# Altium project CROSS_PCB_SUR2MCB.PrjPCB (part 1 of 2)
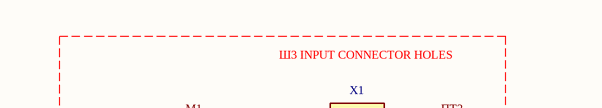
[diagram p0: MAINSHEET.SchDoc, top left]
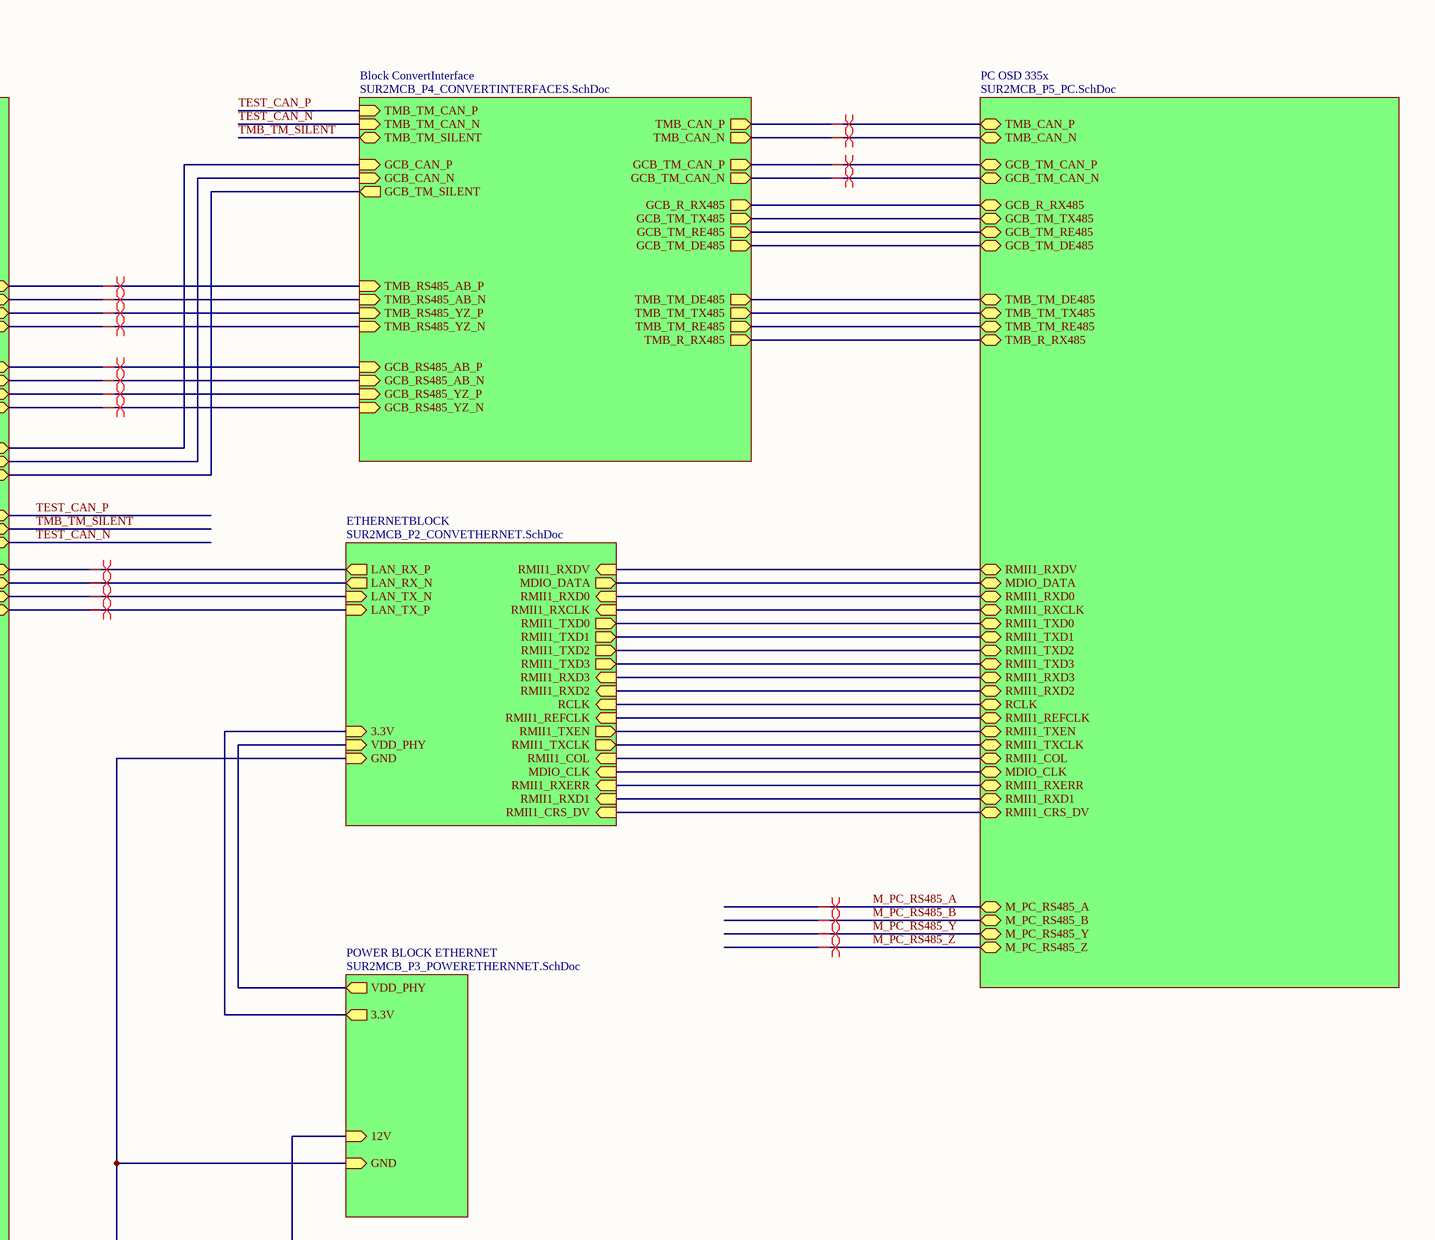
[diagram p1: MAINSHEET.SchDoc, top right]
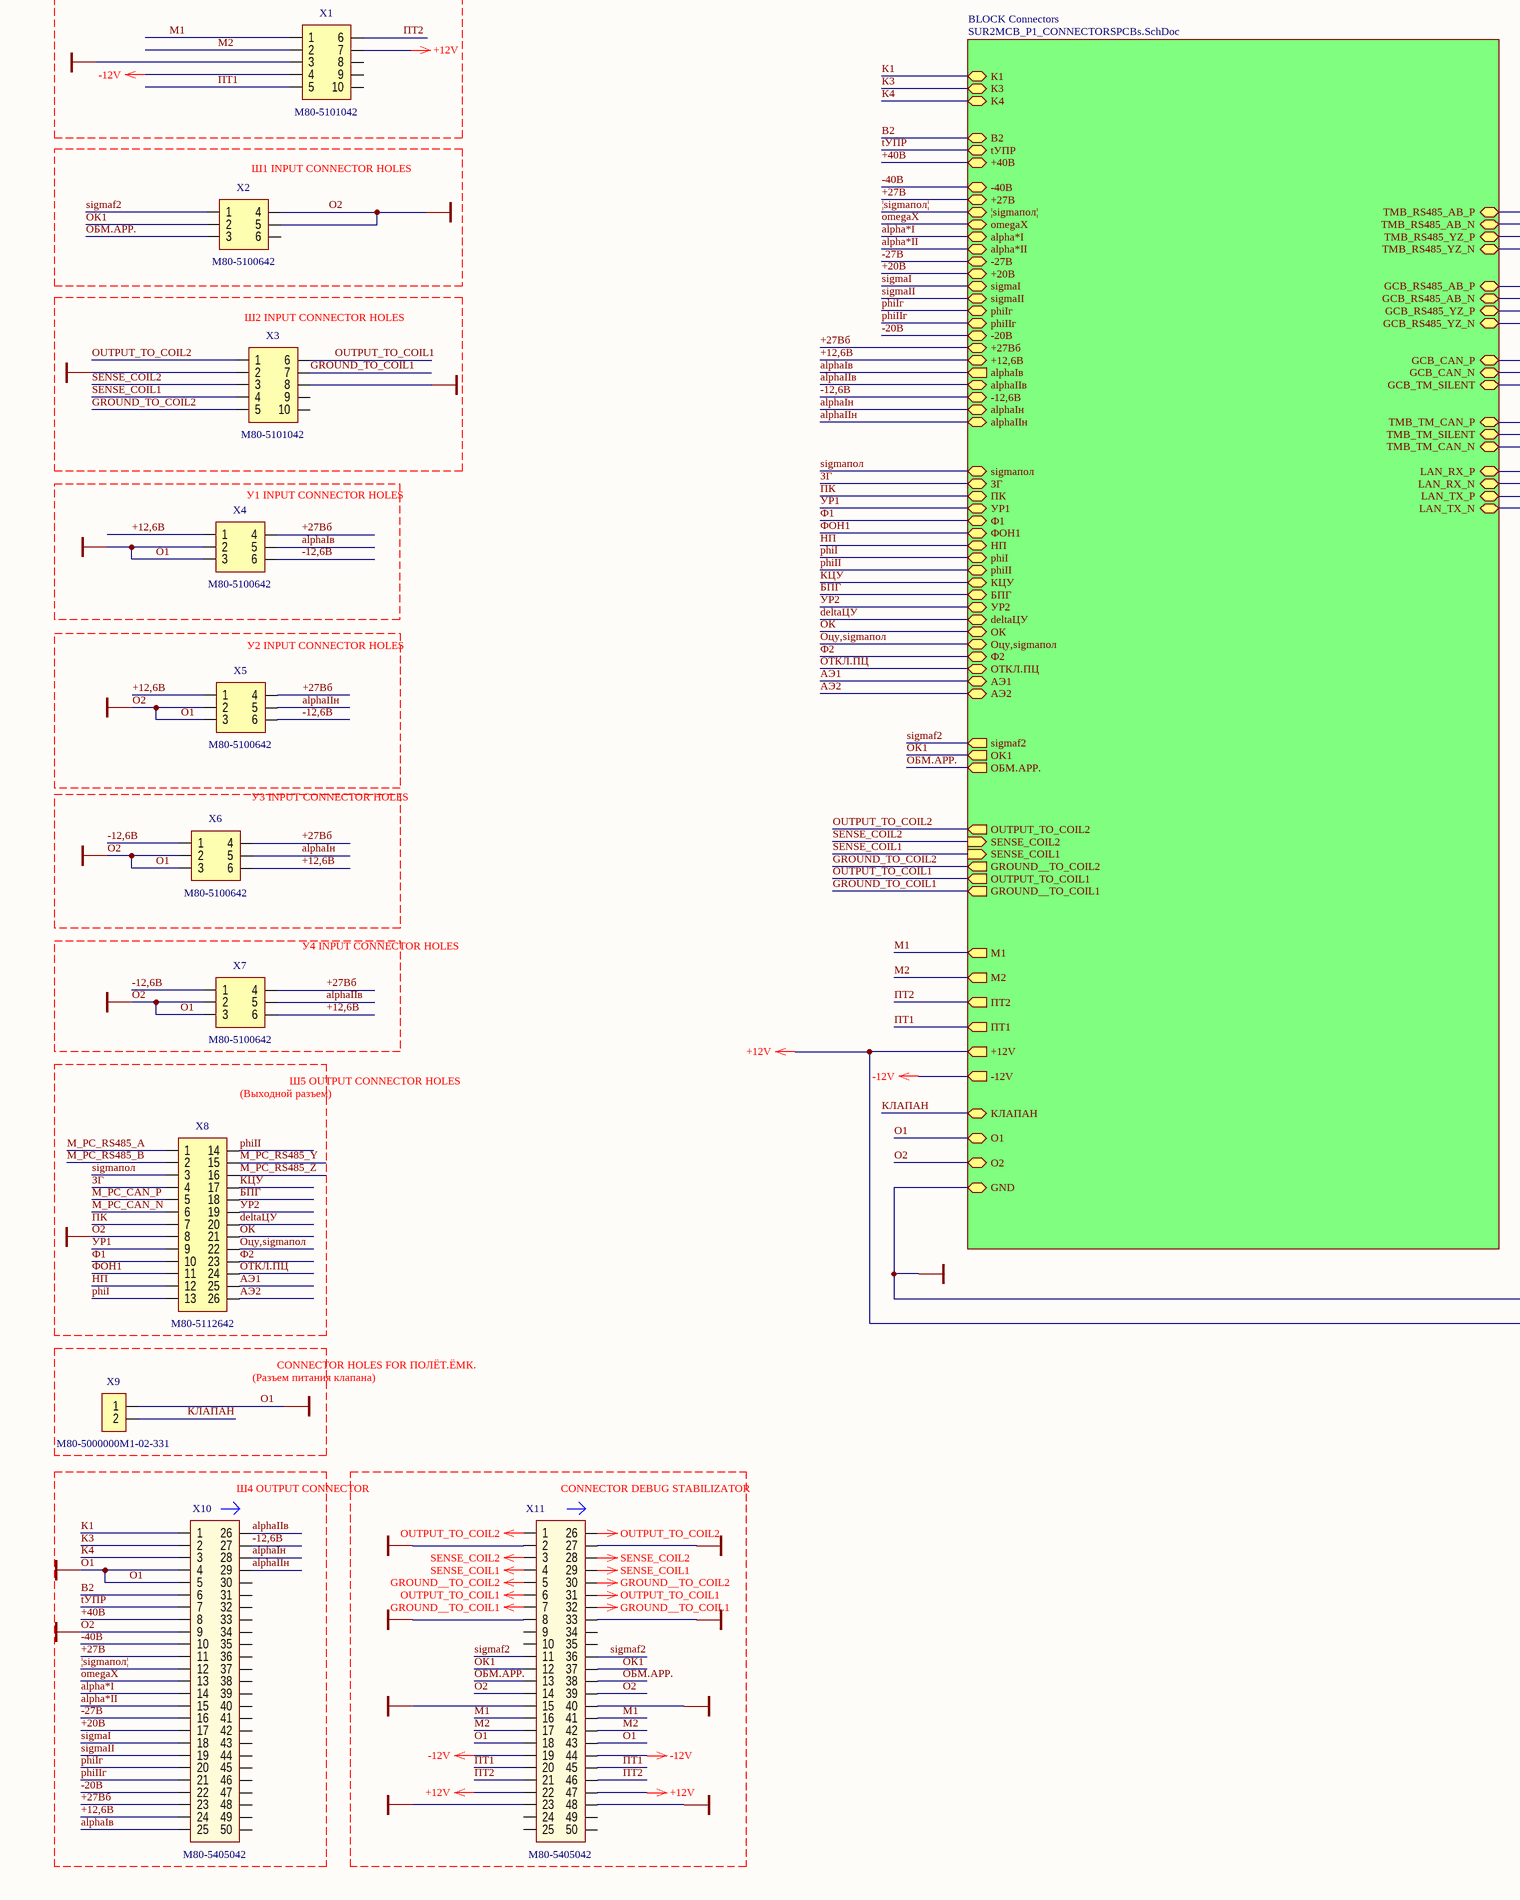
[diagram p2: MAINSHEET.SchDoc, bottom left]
7 sheets, 142 parts. Net scope: hierarchical (ports join the sheet entries above them; power ports are global).
Board file: SUR2MCB.PcbDoc
Sheets:
  MAINSHEET.SchDoc
    BLOCK Connectors = SUR2MCB_P1_CONNECTORSPCBs.SchDoc
    ETHERNETBLOCK = SUR2MCB_P2_CONVETHERNET.SchDoc
    PC OSD 335x = SUR2MCB_P5_PC.SchDoc
    POWER BLOCK ETHERNET = SUR2MCB_P3_POWERETHERNNET.SchDoc
    Block ConvertInterface = SUR2MCB_P4_CONVERTINTERFACES.SchDoc
  Struct_E1.SchDoc

## Sheet MAINSHEET.SchDoc
size 594 x 420 mm; Scale: 1:1; Разраб.: Иванов; Обозначение документа: АБВГ.123456.001 Э3; Пров.: Петров; Утв.: Сидоров; Наименование организации: ОАО "Концерн "МПО-Гидроприбор"; Перв. применение: АБВГ.123456.000; Наименование изделия 1: Плата; Наименование изделия 2: Схема электрическая; Наименование изделия 3: принципиальная; Нач. отд.: Нач. отд.; Фамилия нач. отд.: Сидоров

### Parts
X1  value M80-5101042  [M80-5101042]
X2  value M80-5100642  [M80-5100642]
X3  value M80-5101042  [M80-5101042]
X4  value M80-5100642  [M80-5100642]
X5  value M80-5100642  [M80-5100642]
X6  value M80-5100642  [M80-5100642]
X7  value M80-5100642  [M80-5100642]
X8  value M80-5112642  [M80-5112642_HOR]
X9  value M80-5000000M1-02-331  [M80-5000000M1-02-331]
X10  value M80-5405042  [M80-5405042]
X11  value M80-5405042  [M80-5405042]

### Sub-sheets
BLOCK Connectors = SUR2MCB_P1_CONNECTORSPCBs.SchDoc: tУПР (bidir), B2 (bidir), K4 (bidir), +40В (bidir), К1 (bidir), К3 (bidir), OUTPUT_TO_COIL2 (out), OUTPUT_TO_COIL1 (out), GROUND__TO_COIL1 (out), SENSE_COIL2 (in), GROUND__TO_COIL2 (out), SENSE_COIL1 (in), M1 (out), КЛАПАН (bidir), О1 (bidir), O2 (bidir), TMB_RS485_AB_N (bidir), TMB_RS485_AB_P (bidir), TMB_RS485_YZ_N (bidir), TMB_RS485_YZ_P (bidir), LAN_RX_P (bidir), LAN_RX_N (bidir), LAN_TX_P (bidir), LAN_TX_N (bidir), GCB_RS485_AB_N (bidir), GCB_RS485_YZ_N (bidir), GCB_RS485_YZ_P (bidir), GCB_RS485_AB_P (bidir), GCB_CAN_P (bidir), GCB_CAN_N (bidir), GCB_TM_SILENT (bidir), TMB_TM_CAN_P (bidir), TMB_TM_SILENT (bidir), TMB_TM_CAN_N (bidir), -40В (bidir), +27В (bidir), ¦sigmaпол¦ (bidir), omegaX (bidir), alpha*II (bidir), alpha*I (bidir), -27В (bidir), +20В (bidir), -20В (bidir), sigmaII (bidir), sigmaI (bidir), phiIIг (bidir), phiIг (bidir), +27Вб (bidir), +12,6В (bidir), -12,6В (bidir), alphaIв (out), alphaIIв (bidir), alphaIIн (bidir), alphaIн (bidir), sigmaпол (bidir), ЗГ (bidir), ПК (bidir), УР1 (bidir), Ф1 (bidir), ФОН1 (bidir), НП (bidir), phiI (bidir), phiII (bidir), ПТ2 (out), +12V (out), КЦУ (bidir), БПГ (bidir), УР2 (bidir), deltaЦУ (bidir), ОК (bidir), Оцу,sigmaпол (bidir), Ф2 (bidir), ОТКЛ.ПЦ (bidir), АЭ1 (bidir), АЭ2 (bidir), ПТ1 (out), M2 (out), -12V (out), sigmaf2 (out), OK1 (out), ОБМ.АРР. (out), GND (bidir)
Block ConvertInterface = SUR2MCB_P4_CONVERTINTERFACES.SchDoc: TMB_TM_TX485 (out), GCB_RS485_YZ_P (in), TMB_R_RX485 (out), GCB_RS485_YZ_N (in), GCB_RS485_AB_P (in), TMB_TM_RE485 (out), GCB_TM_CAN_P (out), TMB_TM_DE485 (out), GCB_TM_CAN_N (out), GCB_RS485_AB_N (in), TMB_RS485_YZ_N (in), GCB_TM_RE485 (out), GCB_CAN_P (in), GCB_R_RX485 (out), GCB_TM_TX485 (out), TMB_RS485_AB_P (in), GCB_TM_SILENT (out), GCB_CAN_N (in), TMB_RS485_YZ_P (in), TMB_RS485_AB_N (in), GCB_TM_DE485 (out), TMB_TM_SILENT (bidir), TMB_TM_CAN_P (in), TMB_TM_CAN_N (in), TMB_CAN_P (out), TMB_CAN_N (out)
ETHERNETBLOCK = SUR2MCB_P2_CONVETHERNET.SchDoc: RMII1_RXDV (in), MDIO_DATA (out), RMII1_RXD0 (in), RMII1_RXCLK (in), RMII1_TXD0 (out), RMII1_TXD2 (out), RMII1_TXD3 (out), RMII1_RXD3 (in), RMII1_RXD2 (in), LAN_RX_P (out), RCLK (in), LAN_RX_N (out), LAN_TX_N (in), RMII1_REFCLK (in), RMII1_TXEN (out), LAN_TX_P (in), RMII1_TXCLK (out), RMII1_COL (in), MDIO_CLK (in), RMII1_TXD1 (out), GND (in), VDD_PHY (in), 3.3V (in), RMII1_RXERR (in), RMII1_RXD1 (in), RMII1_CRS_DV (in)
PC OSD 335x = SUR2MCB_P5_PC.SchDoc: GCB_R_RX485 (bidir), GCB_TM_CAN_N (bidir), GCB_TM_RE485 (bidir), GCB_TM_TX485 (bidir), TMB_TM_DE485 (bidir), GCB_TM_DE485 (bidir), TMB_TM_RE485 (bidir), TMB_TM_TX485 (bidir), TMB_R_RX485 (bidir), RMII1_TXCLK (bidir), GCB_TM_CAN_P (bidir), TMB_CAN_N (bidir), TMB_CAN_P (bidir), RMII1_TXD0 (bidir), RMII1_CRS_DV (bidir), RMII1_TXD2 (bidir), MDIO_CLK (bidir), RMII1_RXDV (bidir), RMII1_TXD1 (bidir), RMII1_TXEN (bidir), RMII1_RXD3 (bidir), RMII1_RXERR (bidir), RMII1_TXD3 (bidir), RMII1_RXD0 (bidir), MDIO_DATA (bidir), RMII1_RXD2 (bidir), RMII1_RXD1 (bidir), RMII1_COL (bidir), RMII1_RXCLK (bidir), RMII1_REFCLK (bidir), RCLK (bidir), M_PC_RS485_Z (bidir), M_PC_RS485_Y (bidir), M_PC_RS485_B (bidir), M_PC_RS485_A (bidir)
POWER BLOCK ETHERNET = SUR2MCB_P3_POWERETHERNNET.SchDoc: 12V (in), VDD_PHY (out), 3.3V (out), GND (in)

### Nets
+12V: X1.7 X11.22 X11.47 ; sheet BLOCK Connectors/+12V, sheet POWER BLOCK ETHERNET/12V
-12V: X1.4 X11.19 X11.44 ; sheet BLOCK Connectors/-12V
GROUND_TO_COIL1: X3.7 X11.7 X11.32 ; sheet BLOCK Connectors/GROUND__TO_COIL1  [also labelled GROUND__TO_COIL1]
GROUND_TO_COIL2: X3.5 X11.5 X11.30 ; sheet BLOCK Connectors/GROUND__TO_COIL2  [also labelled GROUND__TO_COIL2]
OUTPUT_TO_COIL1: X3.6 X11.6 X11.31 ; sheet BLOCK Connectors/OUTPUT_TO_COIL1
OUTPUT_TO_COIL2: X3.1 X11.1 X11.26 ; sheet BLOCK Connectors/OUTPUT_TO_COIL2
RMII1_REFCLK: sheet ETHERNETBLOCK/RMII1_REFCLK, sheet PC OSD 335x/RMII1_REFCLK
SENSE_COIL1: X3.4 X11.4 X11.29 ; sheet BLOCK Connectors/SENSE_COIL1
SENSE_COIL2: X3.3 X11.3 X11.28 ; sheet BLOCK Connectors/SENSE_COIL2
VDD_3.3V: sheet ETHERNETBLOCK/3.3V, sheet POWER BLOCK ETHERNET/3.3V
VDD_PHY: sheet ETHERNETBLOCK/VDD_PHY, sheet POWER BLOCK ETHERNET/VDD_PHY
О1: X1.3 X2.4 X2.5 X3.2 X3.8 X4.2 X4.3 X5.2 X5.3 X6.2 X6.3 X7.2 X7.3 X8.8 X9.1 X10.4 X10.5 X10.9 X11.2 X11.8 X11.14 X11.15 X11.18 X11.23 X11.27 X11.33 X11.39 X11.40 X11.43 X11.48 ; sheet BLOCK Connectors/О1, sheet BLOCK Connectors/O2, sheet BLOCK Connectors/GND, sheet ETHERNETBLOCK/GND, sheet POWER BLOCK ETHERNET/GND  [also labelled GND, О2]
+12,6В: X4.1 X5.1 X6.6 X7.6 X10.24 ; sheet BLOCK Connectors/+12,6В
+20В: X10.17 ; sheet BLOCK Connectors/+20В
+27В: X10.11 ; sheet BLOCK Connectors/+27В
+27Вб: X4.4 X5.4 X6.4 X7.4 X10.23 ; sheet BLOCK Connectors/+27Вб
+40В: X10.8 ; sheet BLOCK Connectors/+40В
-12,6В: X4.6 X5.6 X6.1 X7.1 X10.27 ; sheet BLOCK Connectors/-12,6В
-20В: X10.22 ; sheet BLOCK Connectors/-20В
-27В: X10.16 ; sheet BLOCK Connectors/-27В
-40В: X10.10 ; sheet BLOCK Connectors/-40В
alpha*I: X10.14 ; sheet BLOCK Connectors/alpha*I
alpha*II: X10.15 ; sheet BLOCK Connectors/alpha*II
alphaIIв: X4.5 X5.5 X6.5 X7.5 X10.25 X10.26 X10.28 X10.29 ; sheet BLOCK Connectors/alphaIв, sheet BLOCK Connectors/alphaIIв, sheet BLOCK Connectors/alphaIIн, sheet BLOCK Connectors/alphaIн  [also labelled alphaIIн, alphaIв, alphaIн]
deltaЦУ: X8.20 ; sheet BLOCK Connectors/deltaЦУ
GCB_CAN_N: sheet BLOCK Connectors/GCB_CAN_N, sheet Block ConvertInterface/GCB_CAN_N
GCB_CAN_P: sheet BLOCK Connectors/GCB_CAN_P, sheet Block ConvertInterface/GCB_CAN_P
GCB_R_RX485: sheet PC OSD 335x/GCB_R_RX485, sheet Block ConvertInterface/GCB_R_RX485
GCB_RS485_AB_N: sheet BLOCK Connectors/GCB_RS485_AB_N, sheet Block ConvertInterface/GCB_RS485_AB_N
GCB_RS485_AB_P: sheet BLOCK Connectors/GCB_RS485_AB_P, sheet Block ConvertInterface/GCB_RS485_AB_P
GCB_RS485_YZ_N: sheet BLOCK Connectors/GCB_RS485_YZ_N, sheet Block ConvertInterface/GCB_RS485_YZ_N
GCB_RS485_YZ_P: sheet BLOCK Connectors/GCB_RS485_YZ_P, sheet Block ConvertInterface/GCB_RS485_YZ_P
GCB_TM_CAN_N: sheet PC OSD 335x/GCB_TM_CAN_N, sheet Block ConvertInterface/GCB_TM_CAN_N
GCB_TM_CAN_P: sheet PC OSD 335x/GCB_TM_CAN_P, sheet Block ConvertInterface/GCB_TM_CAN_P
GCB_TM_DE485: sheet PC OSD 335x/GCB_TM_DE485, sheet Block ConvertInterface/GCB_TM_DE485
GCB_TM_RE485: sheet PC OSD 335x/GCB_TM_RE485, sheet Block ConvertInterface/GCB_TM_RE485
GCB_TM_SILENT: sheet BLOCK Connectors/GCB_TM_SILENT, sheet Block ConvertInterface/GCB_TM_SILENT
GCB_TM_TX485: sheet PC OSD 335x/GCB_TM_TX485, sheet Block ConvertInterface/GCB_TM_TX485
LAN_RX_N: sheet BLOCK Connectors/LAN_RX_N, sheet ETHERNETBLOCK/LAN_RX_N
LAN_RX_P: sheet BLOCK Connectors/LAN_RX_P, sheet ETHERNETBLOCK/LAN_RX_P
LAN_TX_N: sheet BLOCK Connectors/LAN_TX_N, sheet ETHERNETBLOCK/LAN_TX_P
LAN_TX_N: sheet BLOCK Connectors/LAN_TX_P, sheet ETHERNETBLOCK/LAN_TX_N  [a separate net that carries the same name]
M_PC_CAN_N: X8.6
M_PC_CAN_P: X8.5
M_PC_RS485_A: X8.1 ; sheet PC OSD 335x/M_PC_RS485_A
M_PC_RS485_B: X8.2 ; sheet PC OSD 335x/M_PC_RS485_B
M_PC_RS485_Y: X8.15 ; sheet PC OSD 335x/M_PC_RS485_Y
M_PC_RS485_Z: X8.16 ; sheet PC OSD 335x/M_PC_RS485_Z
MDIO_CLK: sheet ETHERNETBLOCK/MDIO_CLK, sheet PC OSD 335x/MDIO_CLK
MDIO_DATA: sheet ETHERNETBLOCK/MDIO_DATA, sheet PC OSD 335x/MDIO_DATA
omegaX: X10.13 ; sheet BLOCK Connectors/omegaX
phiI: X8.13 ; sheet BLOCK Connectors/phiI
phiII: X8.14 ; sheet BLOCK Connectors/phiII
phiIIг: X10.21 ; sheet BLOCK Connectors/phiIIг
phiIг: X10.20 ; sheet BLOCK Connectors/phiIг
RCLK: sheet ETHERNETBLOCK/RCLK, sheet PC OSD 335x/RCLK
RMII1_COL: sheet ETHERNETBLOCK/RMII1_COL, sheet PC OSD 335x/RMII1_COL
RMII1_CRS_DV: sheet ETHERNETBLOCK/RMII1_CRS_DV, sheet PC OSD 335x/RMII1_CRS_DV
RMII1_RXCLK: sheet ETHERNETBLOCK/RMII1_RXCLK, sheet PC OSD 335x/RMII1_RXCLK
RMII1_RXD0: sheet ETHERNETBLOCK/RMII1_RXD0, sheet PC OSD 335x/RMII1_RXD0
RMII1_RXD1: sheet ETHERNETBLOCK/RMII1_RXD1, sheet PC OSD 335x/RMII1_RXD1
RMII1_RXD2: sheet ETHERNETBLOCK/RMII1_RXD2, sheet PC OSD 335x/RMII1_RXD2
RMII1_RXD3: sheet ETHERNETBLOCK/RMII1_RXD3, sheet PC OSD 335x/RMII1_RXD3
RMII1_RXDV: sheet ETHERNETBLOCK/RMII1_RXDV, sheet PC OSD 335x/RMII1_RXDV
RMII1_RXERR: sheet ETHERNETBLOCK/RMII1_RXERR, sheet PC OSD 335x/RMII1_RXERR
RMII1_TXCLK: sheet ETHERNETBLOCK/RMII1_TXCLK, sheet PC OSD 335x/RMII1_TXCLK
RMII1_TXD0: sheet ETHERNETBLOCK/RMII1_TXD0, sheet PC OSD 335x/RMII1_TXD0
RMII1_TXD1: sheet ETHERNETBLOCK/RMII1_TXD1, sheet PC OSD 335x/RMII1_TXD1
RMII1_TXD2: sheet ETHERNETBLOCK/RMII1_TXD2, sheet PC OSD 335x/RMII1_TXD2
RMII1_TXD3: sheet ETHERNETBLOCK/RMII1_TXD3, sheet PC OSD 335x/RMII1_TXD3
RMII1_TXEN: sheet ETHERNETBLOCK/RMII1_TXEN, sheet PC OSD 335x/RMII1_TXEN
sigmaf2: X2.1 X11.11 X11.36 ; sheet BLOCK Connectors/sigmaf2
sigmaI: X10.18 ; sheet BLOCK Connectors/sigmaI
sigmaII: X10.19 ; sheet BLOCK Connectors/sigmaII
sigmaпол: X8.3 ; sheet BLOCK Connectors/sigmaпол
TEST_CAN_N: sheet BLOCK Connectors/TMB_TM_CAN_N, sheet Block ConvertInterface/TMB_TM_CAN_N
TEST_CAN_P: sheet BLOCK Connectors/TMB_TM_CAN_P, sheet Block ConvertInterface/TMB_TM_CAN_P
TMB_CAN_N: sheet PC OSD 335x/TMB_CAN_N, sheet Block ConvertInterface/TMB_CAN_N
TMB_CAN_P: sheet PC OSD 335x/TMB_CAN_P, sheet Block ConvertInterface/TMB_CAN_P
TMB_R_RX485: sheet PC OSD 335x/TMB_R_RX485, sheet Block ConvertInterface/TMB_R_RX485
TMB_RS485_AB_N: sheet BLOCK Connectors/TMB_RS485_AB_N, sheet Block ConvertInterface/TMB_RS485_AB_N
TMB_RS485_AB_P: sheet BLOCK Connectors/TMB_RS485_AB_P, sheet Block ConvertInterface/TMB_RS485_AB_P
TMB_RS485_YZ_N: sheet BLOCK Connectors/TMB_RS485_YZ_N, sheet Block ConvertInterface/TMB_RS485_YZ_N
TMB_RS485_YZ_P: sheet BLOCK Connectors/TMB_RS485_YZ_P, sheet Block ConvertInterface/TMB_RS485_YZ_P
TMB_TM_DE485: sheet PC OSD 335x/TMB_TM_DE485, sheet Block ConvertInterface/TMB_TM_DE485
TMB_TM_RE485: sheet PC OSD 335x/TMB_TM_RE485, sheet Block ConvertInterface/TMB_TM_RE485
TMB_TM_SILENT: sheet BLOCK Connectors/TMB_TM_SILENT, sheet Block ConvertInterface/TMB_TM_SILENT
TMB_TM_TX485: sheet PC OSD 335x/TMB_TM_TX485, sheet Block ConvertInterface/TMB_TM_TX485
tУПР: X10.7 ; sheet BLOCK Connectors/tУПР
¦sigmaпол¦: X10.12 ; sheet BLOCK Connectors/¦sigmaпол¦
АЭ1: X8.25 ; sheet BLOCK Connectors/АЭ1
АЭ2: X8.26 ; sheet BLOCK Connectors/АЭ2
БПГ: X8.18 ; sheet BLOCK Connectors/БПГ
В2: X10.6 ; sheet BLOCK Connectors/B2
ЗГ: X8.4 ; sheet BLOCK Connectors/ЗГ
К1: X10.1 ; sheet BLOCK Connectors/К1
К3: X10.2 ; sheet BLOCK Connectors/К3
К4: X10.3 ; sheet BLOCK Connectors/K4
КЛАПАН: X9.2 ; sheet BLOCK Connectors/КЛАПАН
КЦУ: X8.17 ; sheet BLOCK Connectors/КЦУ
М1: X1.1 X11.16 X11.41 ; sheet BLOCK Connectors/M1
М2: X1.2 X11.17 X11.42 ; sheet BLOCK Connectors/M2
НП: X8.12 ; sheet BLOCK Connectors/НП
ОБМ.АРР.: X2.3 X11.13 X11.38 ; sheet BLOCK Connectors/ОБМ.АРР.
ОК: X8.21 ; sheet BLOCK Connectors/ОК
ОК1: X2.2 X11.12 X11.37 ; sheet BLOCK Connectors/OK1
ОТКЛ.ПЦ: X8.24 ; sheet BLOCK Connectors/ОТКЛ.ПЦ
Оцу,sigmaпол: X8.22 ; sheet BLOCK Connectors/Оцу,sigmaпол
ПК: X8.7 ; sheet BLOCK Connectors/ПК
ПТ1: X1.5 X11.20 X11.45 ; sheet BLOCK Connectors/ПТ1
ПТ2: X1.6 X11.21 X11.46 ; sheet BLOCK Connectors/ПТ2
УР1: X8.9 ; sheet BLOCK Connectors/УР1
УР2: X8.19 ; sheet BLOCK Connectors/УР2
Ф1: X8.10 ; sheet BLOCK Connectors/Ф1
Ф2: X8.23 ; sheet BLOCK Connectors/Ф2
ФОН1: X8.11 ; sheet BLOCK Connectors/ФОН1

Not connected (* = marked no-connect by the designer): X1 8 9 10; X2 6; X3 9 10; X10 30 31 32 33 34 35 36 37 38 39 40 41 42 43 44 45 46 47 48 49 50; X11 9 10 24 25 34 35 49 50

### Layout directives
differential pair: GCB_RS485_AB_N, GCB_RS485_AB_P, GCB_RS485_YZ_N, GCB_RS485_YZ_P, GCB_TM_CAN_N, GCB_TM_CAN_P, LAN_RX_N, LAN_RX_P, LAN_TX_N, M_PC_RS485_A, M_PC_RS485_B, M_PC_RS485_Y, M_PC_RS485_Z, TMB_CAN_N, TMB_CAN_P, TMB_RS485_AB_N, TMB_RS485_AB_P, TMB_RS485_YZ_N, TMB_RS485_YZ_P

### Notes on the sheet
- Ш3 INPUT CONNECTOR HOLES
- (near X2) Ш1 INPUT CONNECTOR HOLES
- (near X3) Ш2 INPUT CONNECTOR HOLES
- (near X4) У1 INPUT CONNECTOR HOLES
- (near X5) У2 INPUT CONNECTOR HOLES
- (near X6) У3 INPUT CONNECTOR HOLES
- (near X7) У4 INPUT CONNECTOR HOLES
- (Выходной разъем)
- Ш5 OUTPUT CONNECTOR HOLES
- (near X9) CONNECTOR HOLES FOR ПОЛЁТ.ЁМК.
- (near X9) (Разъем питания клапана)
- (near X10) Ш4 OUTPUT CONNECTOR
- (near X11) CONNECTOR DEBUG STABILIZATOR

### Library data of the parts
X1 X3 = M80-5101042: J-TEK 10 POS DIL MALE 2.0MM 2.2A 800V; ValueManufacturer: Harvin Inc.; PowerVoltage: 2.2A, 800V; ValueDescription: M80-5101042 Вилка Harvin Inc.  6.05x20.4mm  2.2A, 800V; ValueType: Connector
X2 X4-X7 = M80-5100642: J-TEK 6 POS DIL MALE 2.0MM 2.2A 800V; ValueManufacturer: Harvin Inc.; PowerVoltage: 2.2A, 800V; ValueDescription: M80-5100642 Вилка Harvin Inc.  6.05x16.4mm  2.2A, 800V; ValueType: Connector
X8 = M80-5112642_HOR: J-TEK 26 POS DIL MALE 2.0MM 2.2A 800V; ValueManufacturer: Harvin Inc.; PowerVoltage: 2.2A, 800V; ValueDescription: M80-5112642 Вилка Harvin Inc.  6.05x36mm  2.2A, 800V; ValueType: Connector
X9 = M80-5000000M1-02-331: MIX-TEK 2 POS DIL MALE 4.0MM 20A 600V; ValueManufacturer: Harvin Inc.; PowerVoltage: 20A, 600V; ValueDescription: M80-5000000M1-02-331 Вилка Harvin Inc.  6.05x18.4mm  20A, 600V; ValueType: Connector
X10 X11 = M80-5405042: CONN HDR 2MM R/A W/SCREW 50POS; ValueManufacturer: Harwin Inc.; PowerVoltage: 2.2A, 800V; TechSpec: 3A; ValueDescription: M80-5405042 Вилка Harwin Inc.  10x60mm  3A; ValueType: Male Socket

## Sheet SUR2MCB_P1_CONNECTORSPCBs.SchDoc
size 420 x 297 mm; Scale: 1:1; Разраб.: Иванов; Обозначение документа: АБВГ.123456.001 Э3; Пров.: Петров; Утв.: Сидоров; Наименование организации: ОАО "Концерн "МПО-Гидроприбор"; Перв. применение: АБВГ.123456.000; Наименование изделия 1: Плата; Наименование изделия 2: Схема электрическая; Наименование изделия 3: принципиальная; Нач. отд.: Нач. отд.; Фамилия нач. отд.: Сидоров
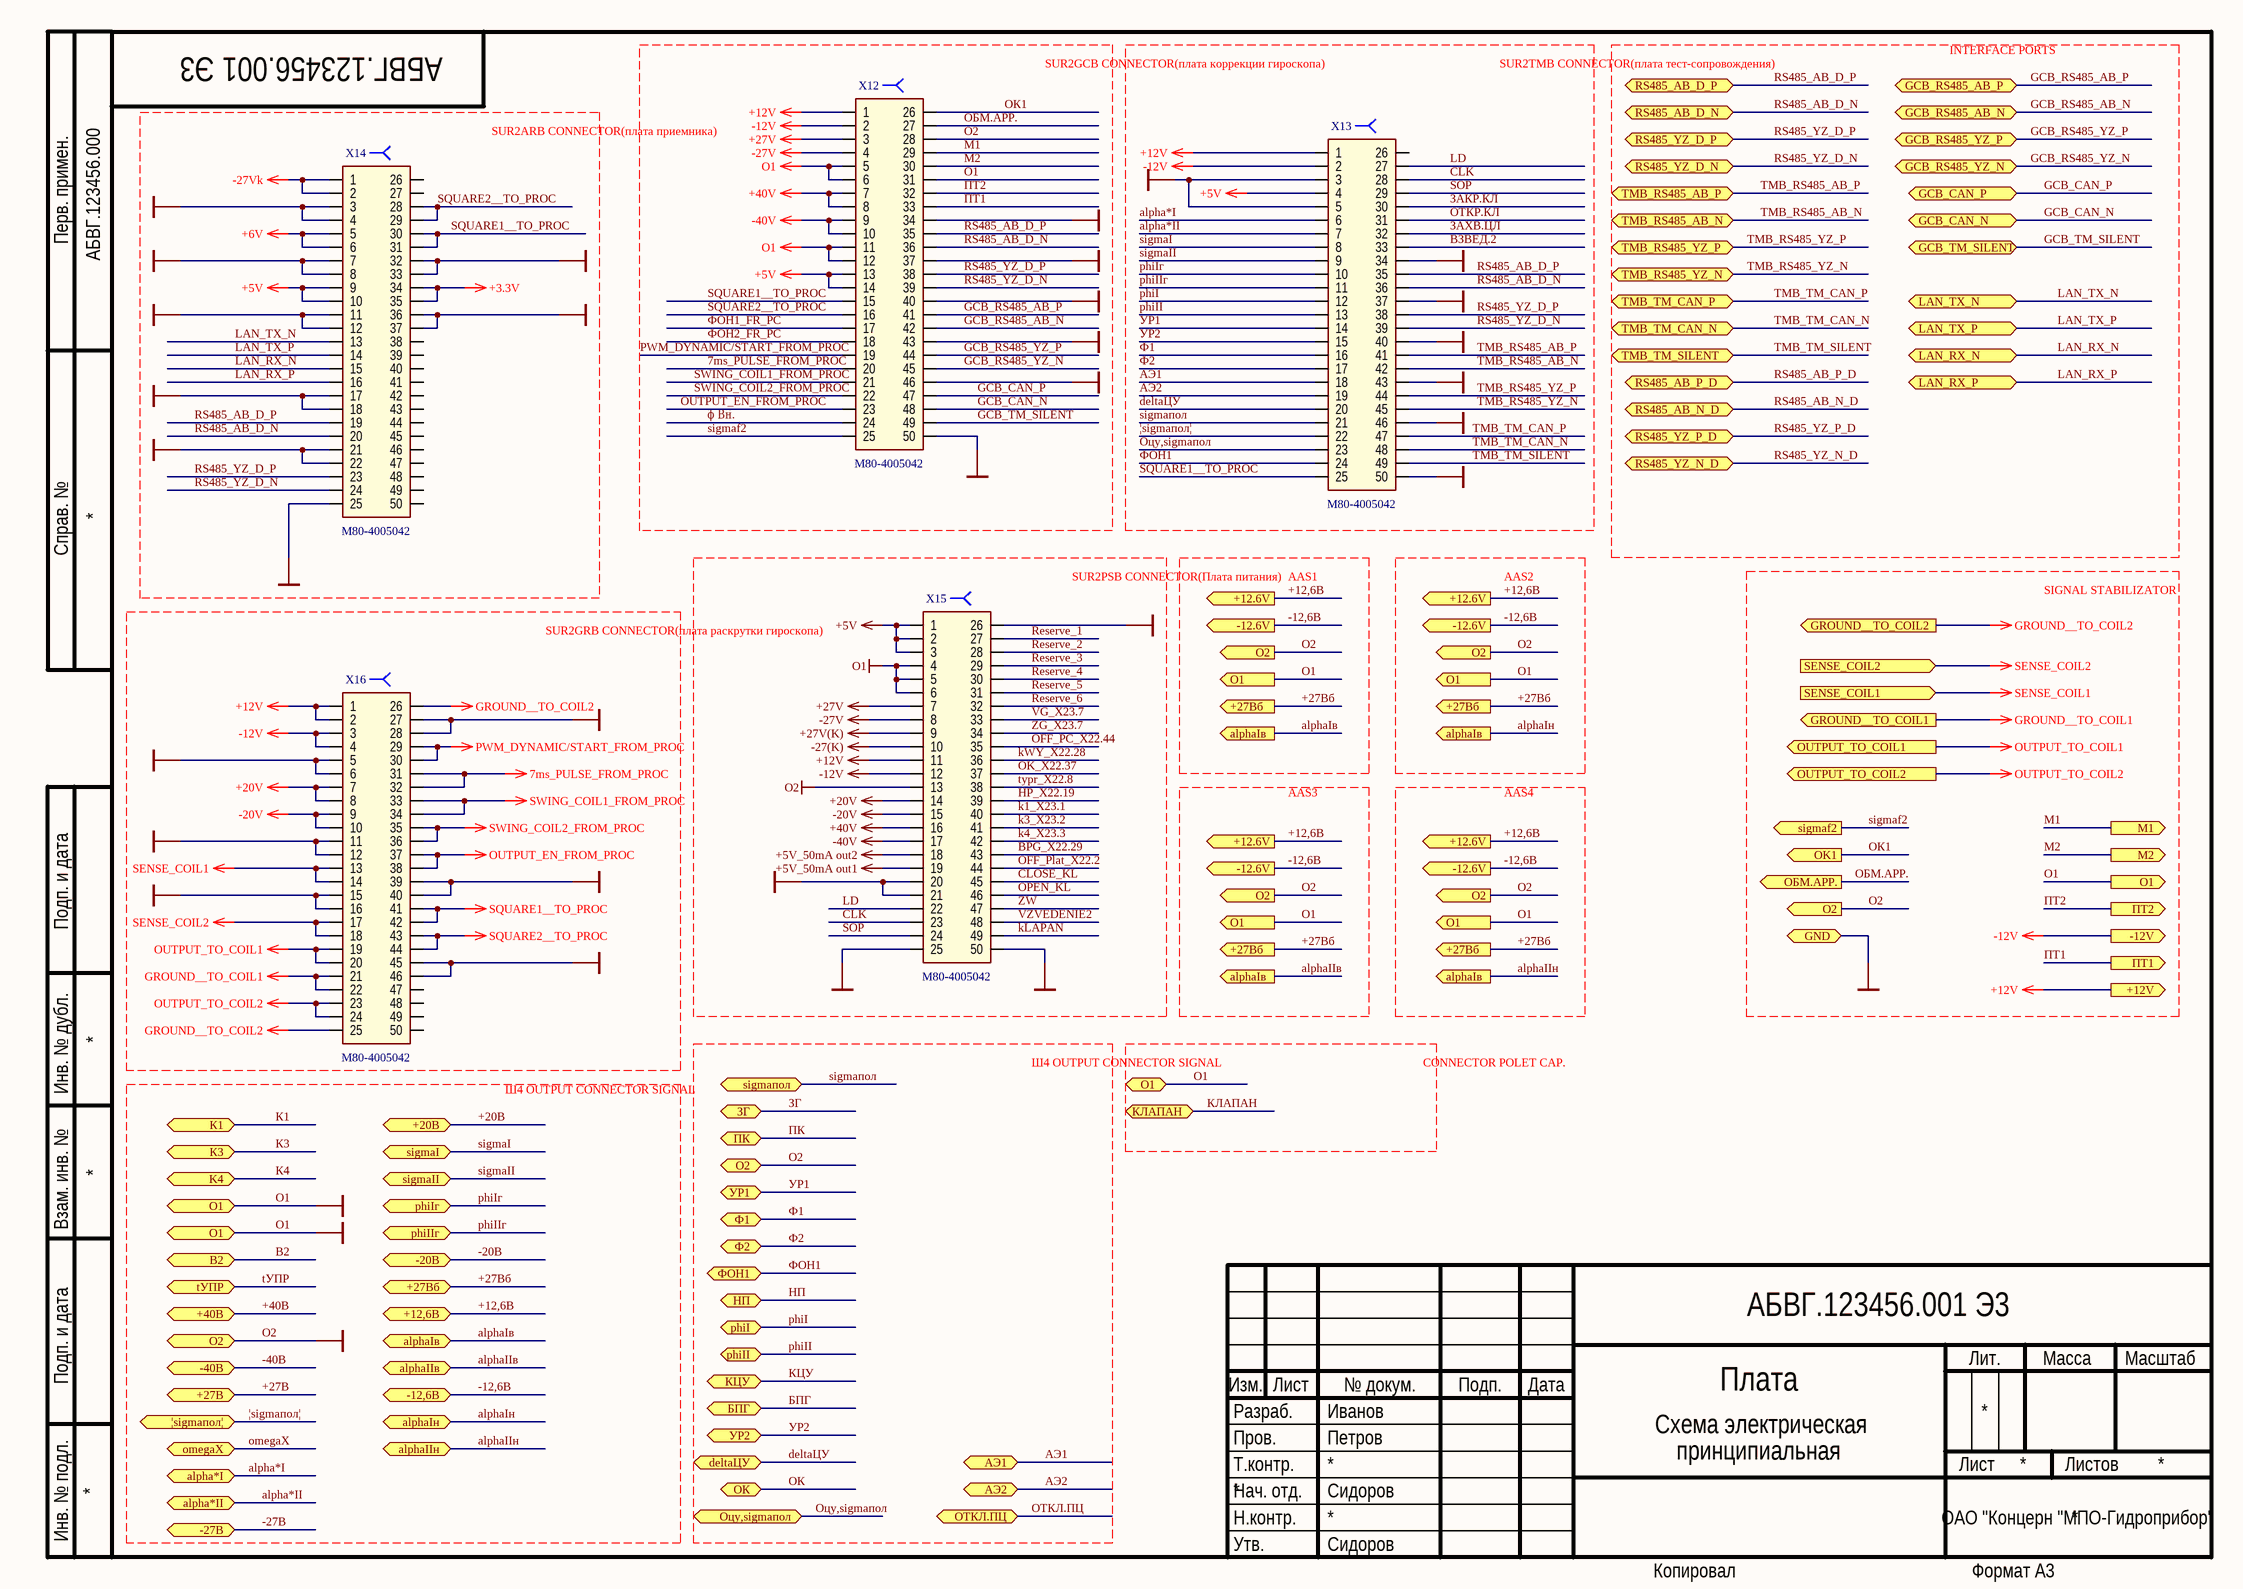
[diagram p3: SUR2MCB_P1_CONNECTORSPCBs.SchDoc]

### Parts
X12  value M80-4005042  [M80-4005042]
X13  value M80-4005042  [M80-4005042]
X14  value M80-4005042  [M80-4005042]
X15  value M80-4005042  [M80-4005042]
X16  value M80-4005042  [M80-4005042]

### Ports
+12,6В (bidir), +12.6V (out), +12V (out), +20В (bidir), +27В (bidir), +27Вб (bidir), +27Вб (out), +40В (bidir), -12,6В (bidir), -12.6V (out), -12V (out), -20В (bidir), -27В (bidir), -40В (bidir), alpha*I (bidir), alpha*II (bidir), alphaIIв (bidir), alphaIIн (bidir), alphaIв (bidir), alphaIв (out), alphaIн (bidir), B2 (bidir), deltaЦУ (bidir), GCB_CAN_N (bidir), GCB_CAN_P (bidir), GCB_RS485_AB_N (bidir), GCB_RS485_AB_P (bidir), GCB_RS485_YZ_N (bidir), GCB_RS485_YZ_P (bidir), GCB_TM_SILENT (bidir), GND (bidir), GROUND__TO_COIL1 (out), GROUND__TO_COIL2 (out), K4 (bidir), LAN_RX_N (bidir), LAN_RX_P (bidir), LAN_TX_N (bidir), LAN_TX_P (bidir), M1 (out), M2 (out), O1 (bidir), O1 (out), O2 (bidir), O2 (out), OK1 (out), omegaX (bidir), OUTPUT_TO_COIL1 (out), OUTPUT_TO_COIL2 (out), phiI (bidir), phiII (bidir), phiIIг (bidir), phiIг (bidir), RS485_AB_D_N (bidir), RS485_AB_D_P (bidir), RS485_AB_N_D (bidir), RS485_AB_P_D (bidir), RS485_YZ_D_N (bidir), RS485_YZ_D_P (bidir), RS485_YZ_N_D (bidir), RS485_YZ_P_D (bidir), SENSE_COIL1 (in), SENSE_COIL2 (in), sigmaf2 (out), sigmaI (bidir), sigmaII (bidir), sigmaпол (bidir), TMB_RS485_AB_N (bidir), TMB_RS485_AB_P (bidir), TMB_RS485_YZ_N (bidir), TMB_RS485_YZ_P (bidir), TMB_TM_CAN_N (bidir), TMB_TM_CAN_P (bidir), TMB_TM_SILENT (bidir), tУПР (bidir), ¦sigmaпол¦ (bidir), АЭ1 (bidir), АЭ2 (bidir), БПГ (bidir), ЗГ (bidir), К1 (bidir), К3 (bidir), КЛАПАН (bidir), КЦУ (bidir), НП (bidir), О1 (bidir), О2 (bidir), ОБМ.АРР. (out), ОК (bidir), ОТКЛ.ПЦ (bidir), Оцу,sigmaпол (bidir), ПК (bidir), ПТ1 (out), ПТ2 (out), УР1 (bidir), УР2 (bidir), Ф1 (bidir), Ф2 (bidir), ФОН1 (bidir)

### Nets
7ms_PULSE_FROM_PROC: X12.20 X16.31 X16.32
+3.3V: X14.34 X14.35
+5V: X12.13 X12.14 X13.4 X14.9 X14.10 X15.1 X15.2 X15.3
+5V_50mA out1: X15.19
+5V_50mA out2: X15.18
+6V: X14.5 X14.6
+12V: X12.1 X13.1 X15.11 X16.1 X16.2 ; port +12V
+20V: X15.14 X16.7 X16.8
+27V: X12.3 X15.7
+27V(K): X15.9
+40V: X12.7 X12.8 X15.16
-12V: X12.2 X13.2 X15.12 X16.3 X16.4 ; port -12V
-20V: X15.15 X16.9 X16.10
-27(K): X15.10
-27V: X12.4 X15.8
-27Vk: X14.1 X14.2
-40V: X12.9 X12.10 X15.17
GROUND__TO_COIL1: X16.21 X16.22 ; port GROUND__TO_COIL1  [project net GROUND_TO_COIL1]
GROUND__TO_COIL2: X16.25 X16.26 ; port GROUND__TO_COIL2  [project net GROUND_TO_COIL2]
OUTPUT_EN_FROM_PROC: X12.23 X16.37 X16.38
OUTPUT_TO_COIL1: X16.19 X16.20 ; port OUTPUT_TO_COIL1
OUTPUT_TO_COIL2: X16.23 X16.24 ; port OUTPUT_TO_COIL2
PWM_DYNAMIC/START_FROM_PROC: X12.19 X16.29 X16.30
SENSE_COIL1: X16.13 X16.14 ; port SENSE_COIL1
SENSE_COIL2: X16.17 X16.18 ; port SENSE_COIL2
SQUARE1__TO_PROC: X12.15 X13.25 X14.30 X14.31 X16.41 X16.42
SQUARE2__TO_PROC: X12.16 X14.28 X14.29 X16.43 X16.44
SWING_COIL1_FROM_PROC: X12.21 X16.33 X16.34
SWING_COIL2_FROM_PROC: X12.22 X16.35 X16.36
О1: X12.5 X12.6 X12.11 X12.12 X12.28 X12.31 X12.34 X12.37 X12.40 X12.43 X12.46 X12.50 X13.3 X13.5 X13.34 X13.37 X13.40 X13.43 X13.46 X13.50 X14.3 X14.4 X14.7 X14.8 X14.11 X14.12 X14.17 X14.18 X14.21 X14.22 X14.25 X14.32 X14.33 X14.36 X14.37 X15.4 X15.5 X15.6 X15.13 X15.20 X15.21 X15.25 X15.26 X15.50 X16.5 X16.6 X16.11 X16.12 X16.15 X16.16 X16.27 X16.28 X16.39 X16.40 X16.45 X16.46 ; port O1, port O2, port О2, port О1, port GND  [also labelled GND, О2]
+12,6В: port +12.6V, port +12,6В
-12,6В: port -12.6V, port -12,6В
alpha*I: X13.6 ; port alpha*I
alpha*II: X13.7 ; port alpha*II
alphaIIв: port alphaIв, port alphaIIв, port alphaIн, port alphaIIн  [also labelled alphaIIн, alphaIв, alphaIн]
BPG_X22.29: X15.43
CLK: X13.28 X15.23
CLOSE_KL: X15.45
deltaЦУ: X13.20 ; port deltaЦУ
GCB_CAN_N: X12.48 ; port GCB_CAN_N
GCB_CAN_P: X12.47 ; port GCB_CAN_P
GCB_RS485_AB_N: X12.42 ; port GCB_RS485_AB_N
GCB_RS485_AB_P: X12.41 ; port GCB_RS485_AB_P
GCB_RS485_YZ_N: X12.45 ; port GCB_RS485_YZ_N
GCB_RS485_YZ_P: X12.44 ; port GCB_RS485_YZ_P
GCB_TM_SILENT: X12.49 ; port GCB_TM_SILENT
HP_X22.19: X15.39
k1_X23.1: X15.40
k3_X23.2: X15.41
k4_X23.3: X15.42
kLAPAN: X15.49
kWY_X22.28: X15.36
LAN_RX_N: X14.15 ; port LAN_RX_N
LAN_RX_P: X14.16 ; port LAN_RX_P
LAN_TX_N: X14.13 ; port LAN_TX_N
LAN_TX_P: X14.14 ; port LAN_TX_P  [project net LAN_TX_N]
LD: X13.27 X15.22
OFF_PC_X22.44: X15.35
OFF_Plat_X22.2: X15.44
OK_X22.37: X15.37
OPEN_KL: X15.46
phiI: X13.12 ; port phiI
phiII: X13.13 ; port phiII
phiIIг: X13.11 ; port phiIIг
phiIг: X13.10 ; port phiIг
Reserve_1: X15.27
Reserve_2: X15.28
Reserve_3: X15.29
Reserve_4: X15.30
Reserve_5: X15.31
Reserve_6: X15.32
RS485_AB_D_N: X12.36 X13.36 X14.20 ; port RS485_AB_D_N
RS485_AB_D_P: X12.35 X13.35 X14.19 ; port RS485_AB_D_P
RS485_YZ_D_N: X12.39 X13.39 X14.24 ; port RS485_YZ_D_N
RS485_YZ_D_P: X12.38 X13.38 X14.23 ; port RS485_YZ_D_P
sigmaf2: X12.25 ; port sigmaf2
sigmaI: X13.8 ; port sigmaI
sigmaII: X13.9 ; port sigmaII
sigmaпол: X13.21 ; port sigmaпол
SOP: X13.29 X15.24
TMB_RS485_AB_N: X13.42 ; port TMB_RS485_AB_N
TMB_RS485_AB_P: X13.41 ; port TMB_RS485_AB_P
TMB_RS485_YZ_N: X13.45 ; port TMB_RS485_YZ_N
TMB_RS485_YZ_P: X13.44 ; port TMB_RS485_YZ_P
TMB_TM_CAN_N: X13.48 ; port TMB_TM_CAN_N  [project net TEST_CAN_N]
TMB_TM_CAN_P: X13.47 ; port TMB_TM_CAN_P  [project net TEST_CAN_P]
TMB_TM_SILENT: X13.49 ; port TMB_TM_SILENT
typr_X22.8: X15.38
VG_X23.7: X15.33
VZVEDENIE2: X15.48
ZG_X23.7: X15.34
ZW: X15.47
¦sigmaпол¦: X13.22 ; port ¦sigmaпол¦
ϕ Вн.: X12.24
АЭ1: X13.18 ; port АЭ1
АЭ2: X13.19 ; port АЭ2
ВЗВЕД.2: X13.33
ЗАКР.КЛ: X13.30
ЗАХВ.ЦЛ: X13.32
М1: X12.29 ; port M1
М2: X12.30 ; port M2
ОБМ.АРР.: X12.27 ; port ОБМ.АРР.
ОК1: X12.26 ; port OK1
ОТКР.КЛ: X13.31
Оцу,sigmaпол: X13.23 ; port Оцу,sigmaпол
ПТ1: X12.33 ; port ПТ1
ПТ2: X12.32 ; port ПТ2
УР1: X13.14 ; port УР1
УР2: X13.15 ; port УР2
Ф1: X13.16 ; port Ф1
Ф2: X13.17 ; port Ф2
ФОН1: X13.24 ; port ФОН1
ФОН1_FR_PC: X12.17
ФОН2_FR_PC: X12.18

Not connected (* = marked no-connect by the designer): X13 26; X14 26 27 38 39 40 41 42 43 44 45 46 47 48 49 50; X16 47 48 49 50

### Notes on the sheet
- INTERFACE PORTS
- (near X12) SUR2GCB CONNECTOR(плата коррекции гироскопа)
- SUR2TMB CONNECTOR(плата тест-сопровождения)
- (near X14) SUR2ARB CONNECTOR(плата приемника)
- (near X15) SUR2PSB CONNECTOR(Плата питания)
- AAS1
- AAS2
- SIGNAL STABILIZATOR
- SUR2GRB CONNECTOR(плата раскрутки гироскопа)
- AAS3
- AAS4
- Ш4 OUTPUT CONNECTOR SIGNAL
- CONNECTOR POLET CAP.

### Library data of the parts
X12-X16 = M80-4005042: 25+25 WAY FEMALE PC TAIL 3MM; ValueManufacturer: Harwin Inc.; PowerVoltage: 120V; TechSpec: 3A; ValueDescription: M80-4005042 Розетка Harwin Inc.  5.55x60mm  3A; ValueType: Female Socket

## Sheet SUR2MCB_P2_CONVETHERNET.SchDoc
size 420 x 297 mm; Scale: 1:1; Разраб.: Иванов; Обозначение документа: АБВГ.123456.001 Э3; Пров.: Петров; Утв.: Сидоров; Наименование организации: ОАО "Концерн "МПО-Гидроприбор"; Перв. применение: АБВГ.123456.000; Наименование изделия 1: Плата; Наименование изделия 2: Схема электрическая; Наименование изделия 3: принципиальная; Нач. отд.: Нач. отд.; Фамилия нач. отд.: Сидоров
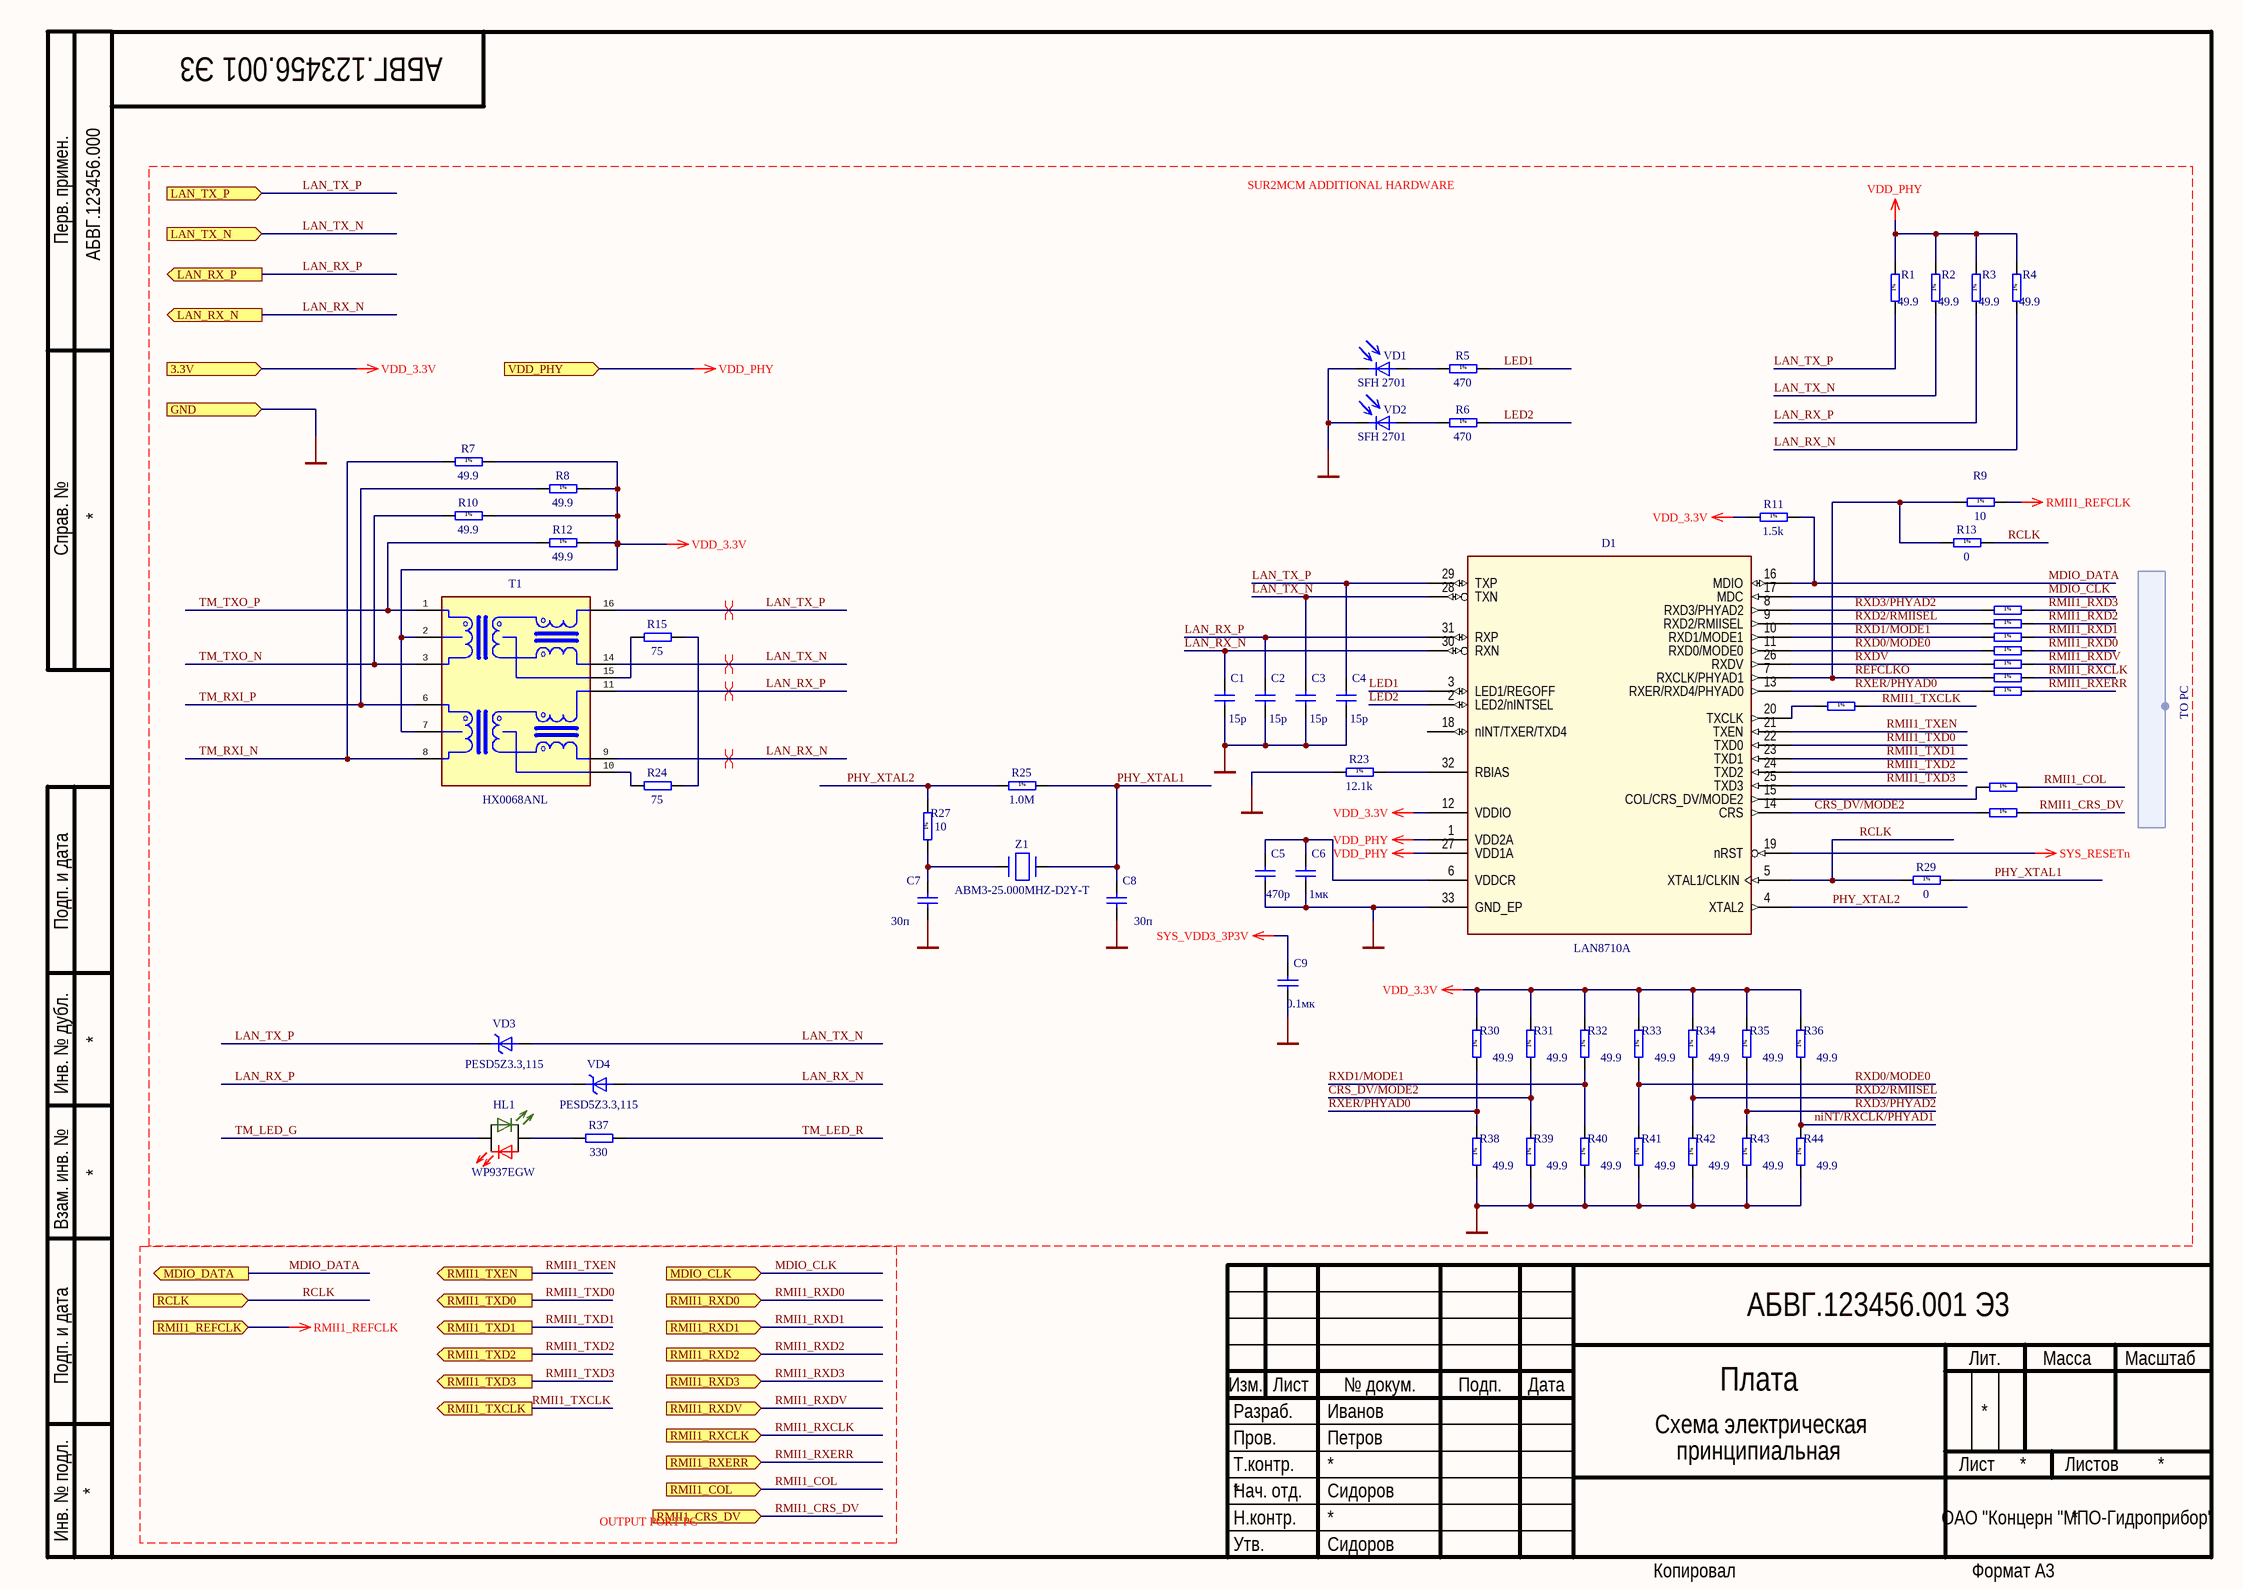
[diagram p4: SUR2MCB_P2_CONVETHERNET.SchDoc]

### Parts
C1  value 15p  [C0603]
C2  value 15p  [C0603]
C3  value 15p  [C0603]
C4  value 15p  [C0603]
C5  value 470p  [C0603]
C6  value 1мк  [C0603]
C7  value 30п  [C0603]
C8  value 30п  [C0603]
C9  value 0.1мк  [C0603]
D1  value LAN8710A  [QFN-32-5X5-0.5-T]
HL1  value WP937EGW  [LED_3MM_ROUND]
R1  value 49.9  [R0603]
R2  value 49.9  [R0603]
R3  value 49.9  [R0603]
R4  value 49.9  [R0603]
R5  value 470  [R0603]
R6  value 470  [R0603]
R7  value 49.9  [R0603]
R8  value 49.9  [R0603]
R9  value 10  [R0603]
R10  value 49.9  [R0603]
R11  value 1.5k  [R0603]
R12  value 49.9  [R0603]
R13  value 0  [R0603]
R14  (no value)  [R0603]
R15  value 75  [R0603]
R16  (no value)  [R0603]
R17  (no value)  [R0603]
R18  (no value)  [R0603]
R19  (no value)  [R0603]
R20  (no value)  [R0603]
R21  (no value)  [R0603]
R22  (no value)  [R0603]
R23  value 12.1k  [R0603]
R24  value 75  [R0603]
R25  value 1.0М  [R0603]
R26  (no value)  [R0603]
R27  value 10  [R0603]
R28  (no value)  [R0603]
R29  value 0  [R0603]
R30  value 49.9  [R0603]
R31  value 49.9  [R0603]
R32  value 49.9  [R0603]
R33  value 49.9  [R0603]
R34  value 49.9  [R0603]
R35  value 49.9  [R0603]
R36  value 49.9  [R0603]
R37  value 330  [R0603]
R38  value 49.9  [R0603]
R39  value 49.9  [R0603]
R40  value 49.9  [R0603]
R41  value 49.9  [R0603]
R42  value 49.9  [R0603]
R43  value 49.9  [R0603]
R44  value 49.9  [R0603]
T1  value HX0068ANL  [HX0068ANL]
VD1  value SFH 2701  [SFH 2701]
VD2  value SFH 2701  [SFH 2701]
VD3  value PESD5Z3.3,115  [SOD-523]
VD4  value PESD5Z3.3,115  [SOD-523]
Z1  value ABM3-25.000MHZ-D2Y-T  [Crystal_2-SMD_(5.0X3.2)]

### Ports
3.3V (in), GND (in), LAN_RX_N (out), LAN_RX_P (out), LAN_TX_N (in), LAN_TX_P (in), MDIO_CLK (in), MDIO_DATA (out), RCLK (in), RMII1_COL (in), RMII1_CRS_DV (in), RMII1_REFCLK (in), RMII1_RXCLK (in), RMII1_RXD0 (in), RMII1_RXD1 (in), RMII1_RXD2 (in), RMII1_RXD3 (in), RMII1_RXDV (in), RMII1_RXERR (in), RMII1_TXCLK (out), RMII1_TXD0 (out), RMII1_TXD1 (out), RMII1_TXD2 (out), RMII1_TXD3 (out), RMII1_TXEN (out), VDD_PHY (in)

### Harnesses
TO PC: 

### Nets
GND: C1.1 C2.1 C3.1 C4.1 C5.1 C6.1 C7.1 C8.1 C9.1 D1.33(GND_EP) R23.2 R38.2 R39.2 R40.2 R41.2 R42.2 R43.2 R44.2 VD1.1(С) VD2.1(С) ; port GND  [project net О1]
RMII1_REFCLK: R9.1 ; port RMII1_REFCLK
SYS_RESETn: D1.19(nRST)
SYS_VDD3_3P3V: C9.2
VDD_3.3V: D1.12(VDDIO) R7.1 R8.1 R10.1 R11.2 R12.1 R30.1 R31.1 R32.1 R33.1 R34.1 R35.1 R36.1 T1.2 T1.7 ; port 3.3V
VDD_PHY: D1.1(VDD2A) D1.27(VDD1A) R1.1 R2.1 R3.1 R4.1 ; port VDD_PHY
CRS_DV/MODE2: D1.14(CRS) R28.2 R31.2 R39.1
LAN_RX_N: C1.2 D1.30(RXN) R4.2 T1.9 VD4.2 ; port LAN_RX_N
LAN_RX_P: C2.2 D1.31(RXP) R3.2 T1.11 VD4.1 ; port LAN_RX_P
LAN_TX_N: C3.2 D1.28(TXN) R2.2 T1.14 VD3.2 ; port LAN_TX_N
LAN_TX_P: C4.2 D1.29(TXP) R1.2 T1.16 VD3.1 ; port LAN_TX_P  [project net LAN_TX_N]
LED1: D1.3(LED1/REGOFF) R5.1
LED2: D1.2(LED2/nINTSEL) R6.1
MDIO_CLK: D1.17(MDC) ; port MDIO_CLK
MDIO_DATA: D1.16(MDIO) R11.1 ; port MDIO_DATA
niNT/RXCLK/PHYAD1: R36.2 R44.1
PHY_XTAL1: C8.2 R25.1 R29.1 Z1.2
PHY_XTAL2: D1.4(XTAL2) R25.2 R27.1
RCLK: D1.5(XTAL1/CLKIN) R13.1 R29.2 ; port RCLK
REFCLKO: D1.7(RXCLK/PHYAD1) R9.2 R13.2 R20.2
RMII1_COL: R26.1 ; port RMII1_COL
RMII1_CRS_DV: R28.1 ; port RMII1_CRS_DV
RMII1_RXCLK: R20.1 ; port RMII1_RXCLK
RMII1_RXD0: R18.1 ; port RMII1_RXD0
RMII1_RXD1: R17.1 ; port RMII1_RXD1
RMII1_RXD2: R16.1 ; port RMII1_RXD2
RMII1_RXD3: R14.1 ; port RMII1_RXD3
RMII1_RXDV: R19.1 ; port RMII1_RXDV
RMII1_RXERR: R21.1 ; port RMII1_RXERR
RMII1_TXCLK: R22.1 ; port RMII1_TXCLK
RMII1_TXD0: D1.22(TXD0) ; port RMII1_TXD0
RMII1_TXD1: D1.23(TXD1) ; port RMII1_TXD1
RMII1_TXD2: D1.24(TXD2) ; port RMII1_TXD2
RMII1_TXD3: D1.25(TXD3) ; port RMII1_TXD3
RMII1_TXEN: D1.21(TXEN) ; port RMII1_TXEN
RXD0/MODE0: D1.11(RXD0/MODE0) R18.2 R33.2 R41.1
RXD1/MODE1: D1.10(RXD1/MODE1) R17.2 R32.2 R40.1
RXD2/RMIISEL: D1.9(RXD2/RMIISEL) R16.2 R34.2 R42.1
RXD3/PHYAD2: D1.8(RXD3/PHYAD2) R14.2 R35.2 R43.1
RXDV: D1.26(RXDV) R19.2
RXER/PHYAD0: D1.13(RXER/RXD4/PHYAD0) R21.2 R30.2 R38.1
TM_LED_G: HL1.1
TM_LED_R: R37.1
TM_RXI_N: R7.2 T1.8
TM_RXI_P: R8.2 T1.6
TM_TXO_N: R10.2 T1.3
TM_TXO_P: R12.2 T1.1
NetC5_2: C5.2 C6.2 D1.6(VDDCR)
NetC7_2: C7.2 R27.2 Z1.1
NetD1_15: D1.15(COL/CRS_DV/MODE2) R26.2
NetD1_20: D1.20(TXCLK) R22.2
NetD1_32: D1.32(RBIAS) R23.1
NetHL1_2: HL1.2 R37.2
NetR5_2: R5.2 VD1.2(A)
NetR6_2: R6.2 VD2.2(A)
NetR15_1: R15.1 R24.1
NetR15_2: R15.2 T1.15
NetR24_2: R24.2 T1.10

Not connected (* = marked no-connect by the designer): D1 18(nINT/TXER/TXD4)

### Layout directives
differential pair: LAN_RX_N, LAN_RX_P, LAN_TX_N

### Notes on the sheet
- SUR2MCM ADDITIONAL HARDWARE
- OUTPUT PORT PC

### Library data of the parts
C1-C4 = C-0603: SMD X7R 0603 25В ±10%; ValueManufacturer: Murata Electronics; ValueManufacturerPartNumber: GCM188R71H; ValueDescription: X7R 0603 (1608)  25В  15pФ ±10%; ValueType: Ceramic Capacitor
C5 = C-0603: SMD X7R 0603 25В ±10%; ValueManufacturer: Murata Electronics; ValueManufacturerPartNumber: GCM188R71H; ValueDescription: X7R 0603 (1608)  25В  470pФ ±10%; ValueType: Ceramic Capacitor
C6 = C-0603: SMD X7R 0603 25В ±10%; ValueManufacturer: Murata Electronics; ValueManufacturerPartNumber: GCM188R71H; ValueDescription: X7R 0603 (1608)  25В  1мкФ ±10%; ValueType: Ceramic Capacitor
C7 C8 = C-0603: SMD X7R 0603 25В ±10%; ValueManufacturer: Murata Electronics; ValueManufacturerPartNumber: GCM188R71H; ValueDescription: X7R 0603 (1608)  25В  30пФ ±10%; ValueType: Ceramic Capacitor
C9 = C-0603: SMD X7R 0603 25В ±10%; ValueManufacturer: Murata Electronics; ValueManufacturerPartNumber: GCM188R71H; ValueDescription: X7R 0603 (1608)  25В  0.1мкФ ±10%; ValueType: Ceramic Capacitor
D1 = LAN8710A: Ethernet ICs 10/100 Ethernet XCVR w/HPAutoMDIX FlexPwr; ValueManufacturer: Texas Instruments; PowerVoltage: 1.6V~3.6V; ValueDescription: LAN8710A ethetnet приемопередатчик 1.6V~3.6V  32-VQFN(5x5); ValueType: transceiver
HL1 = LED_3MM_2COLOR: LED GRN/RED DIFF 3MM ROUND; ValueManufacturer: Kingbright; PowerVoltage: 2.2V / 2V; TechSpec: Зеленый/Красный; ValueDescription: WP937EGW Свтетодиод Radial 3mm  2.2V / 2V  Зеленый/Красный; ValueType: Radial 3mm Led Diode
R1-R4 R7 R8 R10 R12 R30-R36 R38-R44 = R-0603-1%: SMD 0603 0.1Вт ±1% 75В; ValueManufacturer: Panasonic; ValueManufacturerPartNumber: ERJ-3EK; PowerVoltage: 0.1Вт 75В; ValueDescription: 0603 (1608)  0.1Вт 75В  49.9Ом ±1%; ValueType: Chip Resistor
R5 R6 = R-0603-1%: SMD 0603 0.1Вт ±1% 75В; ValueManufacturer: Panasonic; ValueManufacturerPartNumber: ERJ-3EK; PowerVoltage: 0.1Вт 75В; ValueDescription: 0603 (1608)  0.1Вт 75В  470Ом ±1%; ValueType: Chip Resistor
R9 R27 = R-0603-1%: SMD 0603 0.1Вт ±1% 75В; ValueManufacturer: Panasonic; ValueManufacturerPartNumber: ERJ-3EK; PowerVoltage: 0.1Вт 75В; ValueDescription: 0603 (1608)  0.1Вт 75В  10Ом ±1%; ValueType: Chip Resistor
R11 = R-0603-1%: SMD 0603 0.1Вт ±1% 75В; ValueManufacturer: Panasonic; ValueManufacturerPartNumber: ERJ-3EK; PowerVoltage: 0.1Вт 75В; ValueDescription: 0603 (1608)  0.1Вт 75В  1.5kОм ±1%; ValueType: Chip Resistor
R13 R29 = R-0603-1%: SMD 0603 0.1Вт ±1% 75В; ValueManufacturer: Panasonic; ValueManufacturerPartNumber: ERJ-3EK; PowerVoltage: 0.1Вт 75В; ValueDescription: 0603 (1608)  0.1Вт 75В  0Ом ±1%; ValueType: Chip Resistor
R14 R16-R22 R26 R28 = R-0603-1%: SMD 0603 0.1Вт ±1% 75В; ValueManufacturer: Panasonic; ValueManufacturerPartNumber: ERJ-3EK; PowerVoltage: 0.1Вт 75В; ValueDescription: 0603 (1608)  0.1Вт 75В  100Ом ±1%; ValueType: Chip Resistor; Value: 100
R15 R24 = R-0603-5%: SMD 0603 0.1Вт ±5% 75В; ValueManufacturer: Panasonic; ValueManufacturerPartNumber: ERJ-3GE; PowerVoltage: 0.1Вт 75В; ValueDescription: 0603 (1608)  0.1Вт 75В  75Ом ±5%; ValueType: Chip Resistor
R23 = R-0603-1%: SMD 0603 0.1Вт ±1% 75В; ValueManufacturer: Panasonic; ValueManufacturerPartNumber: ERJ-3EK; PowerVoltage: 0.1Вт 75В; ValueDescription: 0603 (1608)  0.1Вт 75В  12.1kОм ±1%; ValueType: Chip Resistor
R25 = R-0603-1%: SMD 0603 0.1Вт ±1% 75В; ValueManufacturer: Panasonic; ValueManufacturerPartNumber: ERJ-3EK; PowerVoltage: 0.1Вт 75В; ValueDescription: 0603 (1608)  0.1Вт 75В  1.0МОм ±1%; ValueType: Chip Resistor
R37 = R-0603-5%: SMD 0603 0.1Вт ±5% 75В; ValueManufacturer: Panasonic; ValueManufacturerPartNumber: ERJ-3GE; PowerVoltage: 0.1Вт 75В; ValueDescription: 0603 (1608)  0.1Вт 75В  330Ом ±5%; ValueType: Chip Resistor
T1 = HX0068ANL: LAN 10/100 Base-T PULSE XFMR 1CT:1CT; ValueManufacturer: Pulse Electronics Network; PowerVoltage: 350мкГн; TechSpec: Высота 2.08mm; ValueDescription: HX0068ANL Трансформатор LAN 10/100 12.70x8.81mm  350мкГн    Высота 2.08mm
VD1 VD2 = SFH 2701: PHOTODIODE PIN 820NM SMD; ValueManufacturer: OSRAM Opto Semiconductors Inc; ValueDescription: SFH 2701  2-SMD
VD3 VD4 = PESD5ZXX: TVS DIODE 3.3V 18VC SOD523; ValueManufacturer: Nexperia USA; PowerVoltage: 18V, 260kW; ValueDescription: PESD5Z3.3,115 TVS диод 18V, 260kW  SOD-523
Z1 = CRYSTAL_2-SMD_ABM3: CRYSTAL 2-SMD ±20PPM 18PF 60Ohm; ValueManufacturer: Abracon LLC; ValueManufacturerPartNumber: ABM3-24.000MHZ-D2Y-T; ValueDescription: ABM3-24.000MHZ-D2Y-T  Кварцевый генератор 2-SMD (5.00x3.20mm)  ±20ppm

## Sheet SUR2MCB_P5_PC.SchDoc
size 420 x 297 mm; Scale: 1:1; Обозначение документа: АБВГ.123456.001 Э3
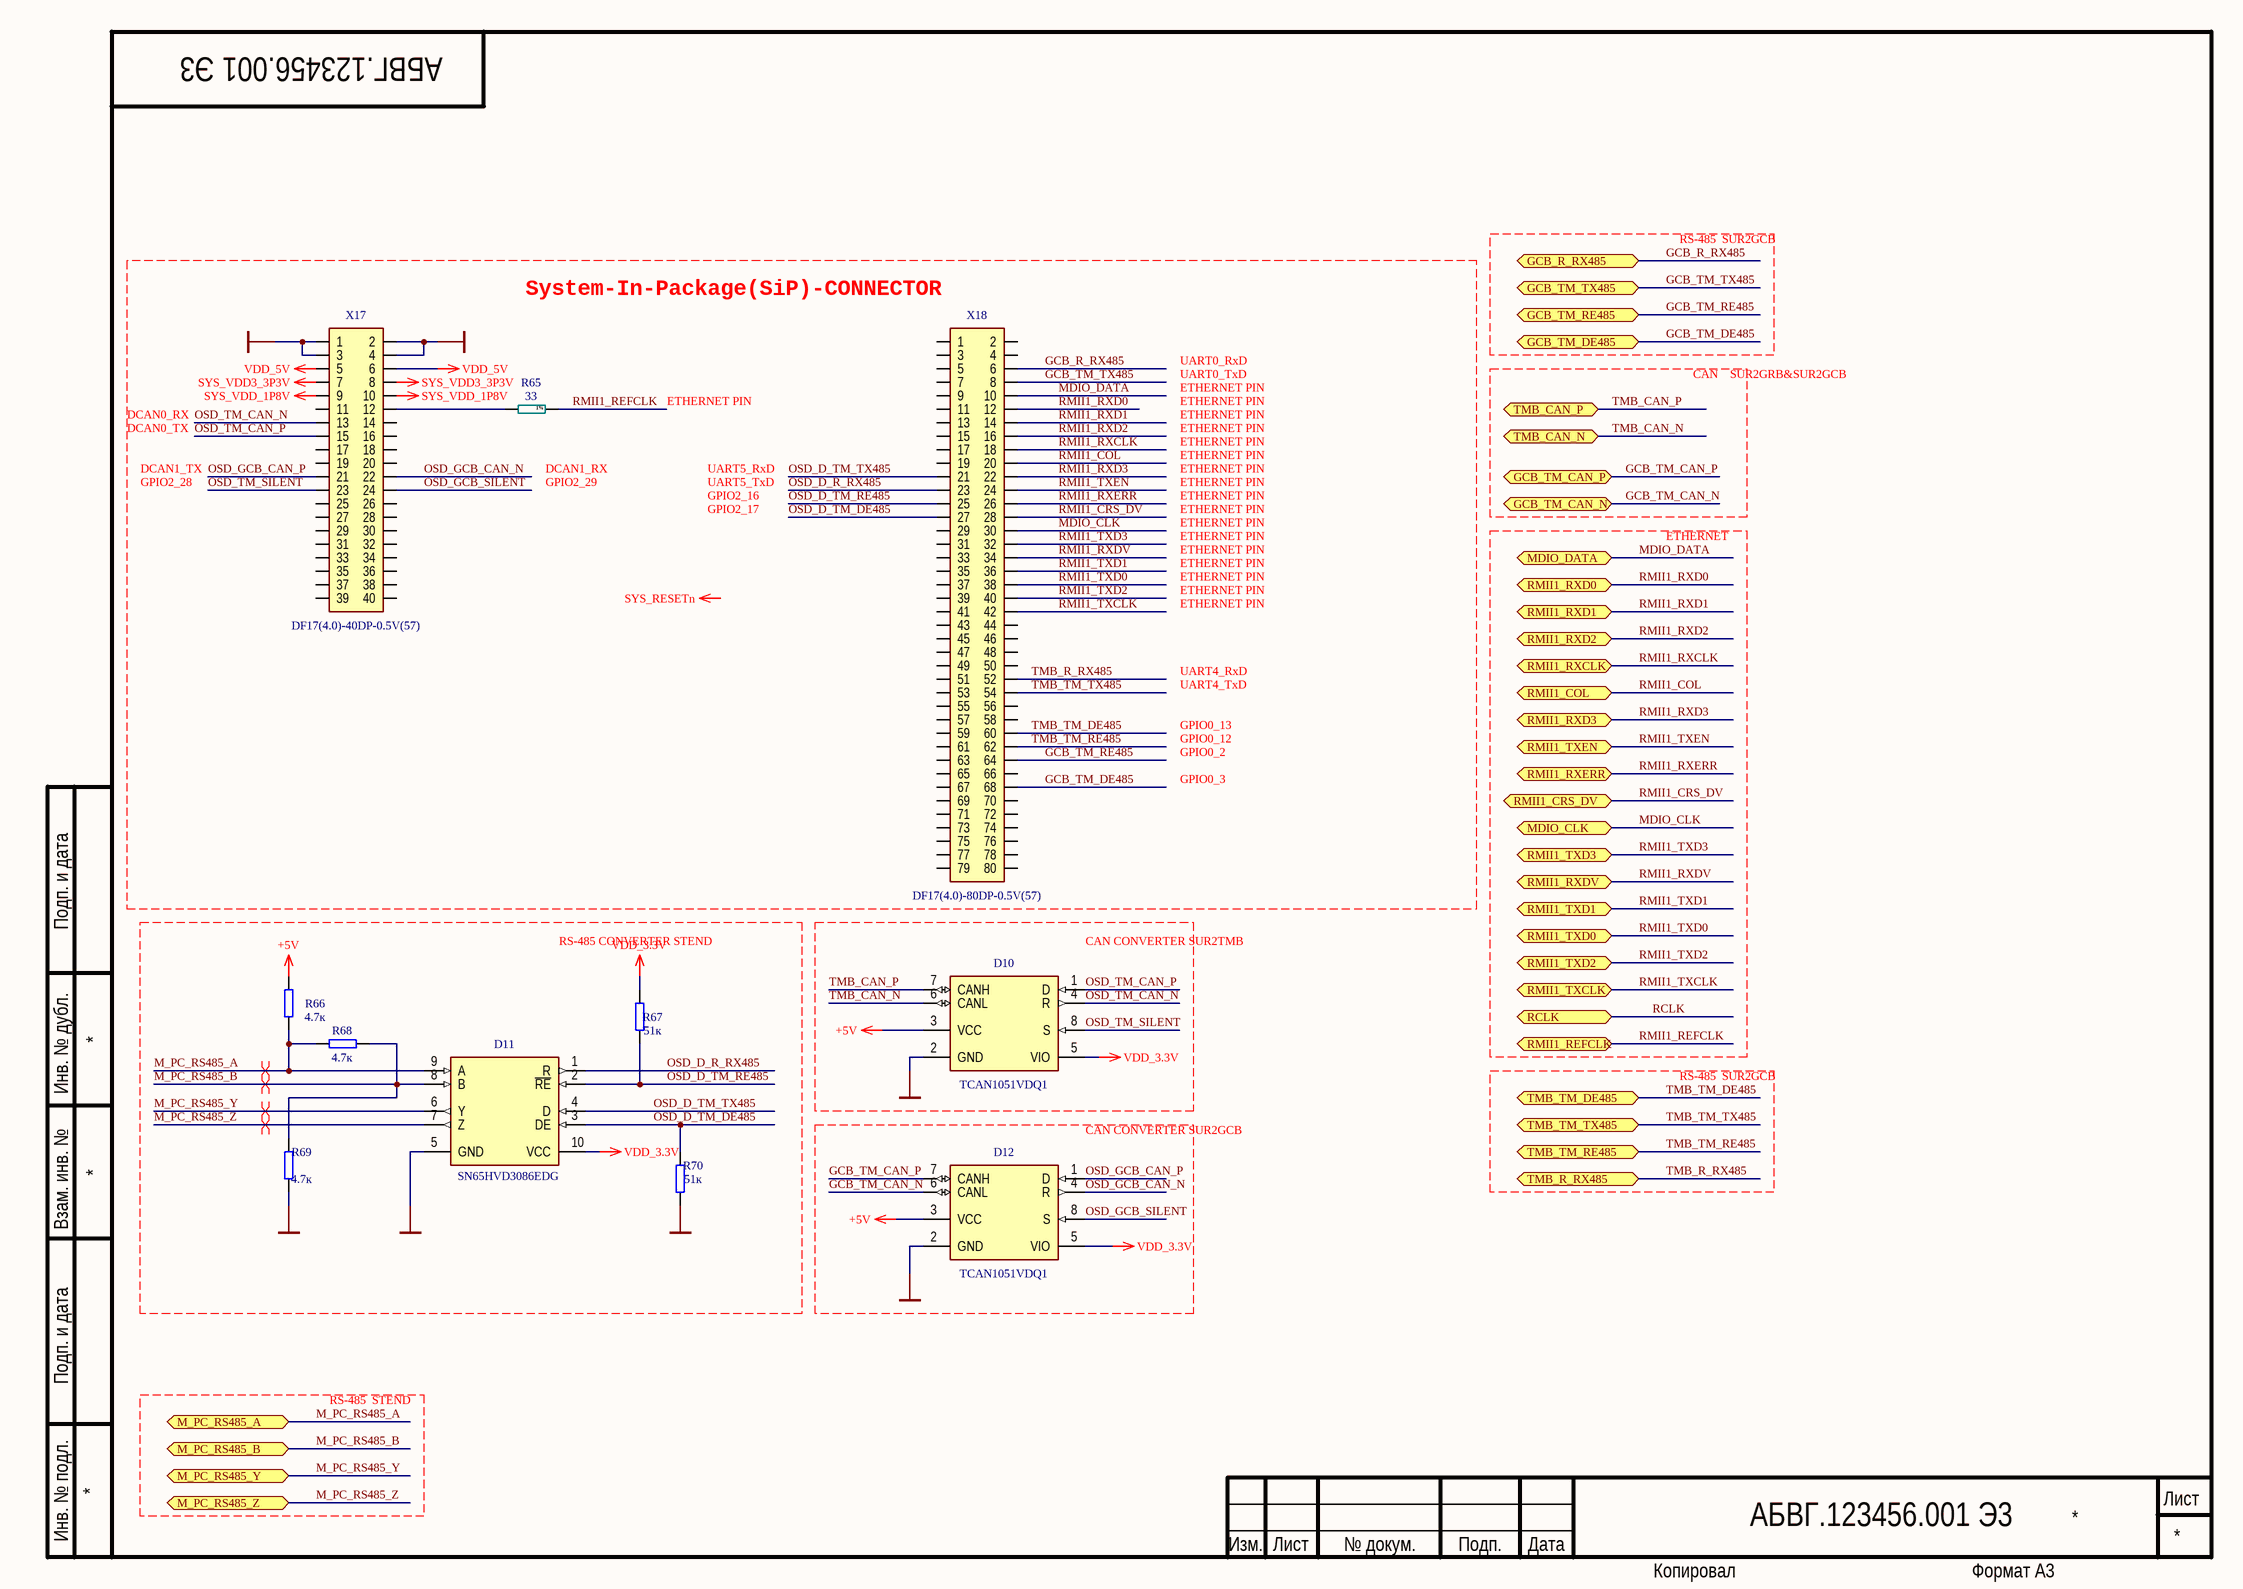
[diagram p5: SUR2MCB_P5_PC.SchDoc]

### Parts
D10  value TCAN1051VDQ1  [SOP-8-3.9X5-1.27]
D11  value SN65HVD3086EDG  [MSOP-10-3X3-0.5]
D12  value TCAN1051VDQ1  [SOP-8-3.9X5-1.27]
R65  value 33  [R0402]
R66  value 4.7к  [R0603]
R67  value 51к  [R0603]
R68  value 4.7к  [R0603]
R69  value 4.7к  [R0603]
R70  value 51к  [R0603]
X17  value DF17(4.0)-40DP-0.5V(57)  [DF17(4.0)-40DP-0.5V(57)]
X18  value DF17(4.0)-80DP-0.5V(57)  [DF17(4.0)-80DP-0.5V(57)]

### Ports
GCB_R_RX485 (bidir), GCB_TM_CAN_N (bidir), GCB_TM_CAN_P (bidir), GCB_TM_DE485 (bidir), GCB_TM_RE485 (bidir), GCB_TM_TX485 (bidir), M_PC_RS485_A (bidir), M_PC_RS485_B (bidir), M_PC_RS485_Y (bidir), M_PC_RS485_Z (bidir), MDIO_CLK (bidir), MDIO_DATA (bidir), RCLK (bidir), RMII1_COL (bidir), RMII1_CRS_DV (bidir), RMII1_REFCLK (bidir), RMII1_RXCLK (bidir), RMII1_RXD0 (bidir), RMII1_RXD1 (bidir), RMII1_RXD2 (bidir), RMII1_RXD3 (bidir), RMII1_RXDV (bidir), RMII1_RXERR (bidir), RMII1_TXCLK (bidir), RMII1_TXD0 (bidir), RMII1_TXD1 (bidir), RMII1_TXD2 (bidir), RMII1_TXD3 (bidir), RMII1_TXEN (bidir), TMB_CAN_N (bidir), TMB_CAN_P (bidir), TMB_R_RX485 (bidir), TMB_TM_DE485 (bidir), TMB_TM_RE485 (bidir), TMB_TM_TX485 (bidir)

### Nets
+5V: D10.3(VCC) D12.3(VCC) R66.1
GND: D10.2(GND) D11.5(GND) D12.2(GND) R69.2 R70.2 X17.1 X17.2 X17.3 X17.4  [project net О1]
RMII1_REFCLK: R65.2 ; port RMII1_REFCLK
SYS_VDD3_3P3V: X17.7 X17.8
SYS_VDD_1P8V: X17.9 X17.10
VDD_3.3V: D10.5(VIO) D11.10(VCC) D12.5(VIO) R67.2
VDD_5V: X17.5 X17.6
GCB_R_RX485: X18.6 ; port GCB_R_RX485
GCB_TM_CAN_N: D12.6(CANL) ; port GCB_TM_CAN_N
GCB_TM_CAN_P: D12.7(CANH) ; port GCB_TM_CAN_P
GCB_TM_DE485: X18.68 ; port GCB_TM_DE485
GCB_TM_RE485: X18.64 ; port GCB_TM_RE485
GCB_TM_TX485: X18.8 ; port GCB_TM_TX485
M_PC_RS485_A: D11.9(A) R66.2 R68.2 ; port M_PC_RS485_A
M_PC_RS485_B: D11.8(B) R68.1 R69.1 ; port M_PC_RS485_B
M_PC_RS485_Y: D11.6(Y) ; port M_PC_RS485_Y
M_PC_RS485_Z: D11.7(Z) ; port M_PC_RS485_Z
MDIO_CLK: X18.30 ; port MDIO_CLK
MDIO_DATA: X18.10 ; port MDIO_DATA
OSD_D_R_RX485: D11.1(R) X18.23
OSD_D_TM_DE485: D11.3(DE) R70.1 X18.27
OSD_D_TM_RE485: D11.2(~{RE}) R67.1 X18.25
OSD_D_TM_TX485: D11.4(D) X18.21
OSD_GCB_CAN_N: D12.4(R) X17.22
OSD_GCB_CAN_P: D12.1(D) X17.21
OSD_GCB_SILENT: D12.8(S) X17.24
OSD_TM_CAN_N: D10.4(R) X17.13
OSD_TM_CAN_P: D10.1(D) X17.15
OSD_TM_SILENT: D10.8(S) X17.23
RMII1_COL: X18.20 ; port RMII1_COL
RMII1_CRS_DV: X18.28 ; port RMII1_CRS_DV
RMII1_RXCLK: X18.18 ; port RMII1_RXCLK
RMII1_RXD0: X18.12 ; port RMII1_RXD0
RMII1_RXD1: X18.14 ; port RMII1_RXD1
RMII1_RXD2: X18.16 ; port RMII1_RXD2
RMII1_RXD3: X18.22 ; port RMII1_RXD3
RMII1_RXDV: X18.34 ; port RMII1_RXDV
RMII1_RXERR: X18.26 ; port RMII1_RXERR
RMII1_TXCLK: X18.42 ; port RMII1_TXCLK
RMII1_TXD0: X18.38 ; port RMII1_TXD0
RMII1_TXD1: X18.36 ; port RMII1_TXD1
RMII1_TXD2: X18.40 ; port RMII1_TXD2
RMII1_TXD3: X18.32 ; port RMII1_TXD3
RMII1_TXEN: X18.24 ; port RMII1_TXEN
TMB_CAN_N: D10.6(CANL) ; port TMB_CAN_N
TMB_CAN_P: D10.7(CANH) ; port TMB_CAN_P
TMB_R_RX485: X18.52 ; port TMB_R_RX485
TMB_TM_DE485: X18.60 ; port TMB_TM_DE485
TMB_TM_RE485: X18.62 ; port TMB_TM_RE485
TMB_TM_TX485: X18.54 ; port TMB_TM_TX485
NetR65_1: R65.1 X17.12

Not connected (* = marked no-connect by the designer): X17 11 14 16 17 18 19 20 25 26 27 28 29 30 31 32 33 34 35 36 37 38 39 40; X18 1 2 3 4 5 7 9 11 13 15 17 19 29 31 33 35 37 39 41 43 44 45 46 47 48 49 50 51 53 55 56 57 58 59 61 63 65 66 67 69 70 71 72 73 74 75 76 77 78 79 80

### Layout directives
differential pair: M_PC_RS485_A, M_PC_RS485_B, M_PC_RS485_Y, M_PC_RS485_Z

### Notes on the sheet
- RS-485  SUR2GCB
- System-In-Package(SiP)-CONNECTOR
- UART0_RxD
- UART0_TxD
- ETHERNET PIN
- CAN    SUR2GRB&SUR2GCB
- DCAN0_RX
- DCAN0_TX
- DCAN1_TX
- GPIO2_28
- DCAN1_RX
- GPIO2_29
- UART5_RxD
- UART5_TxD
- GPIO2_16
- GPIO2_17
- ETHERNET
- UART4_RxD
- UART4_TxD
- GPIO0_13
- GPIO0_12
- GPIO0_2
- GPIO0_3
- RS-485 CONVERTER STEND
- (near D10) CAN CONVERTER SUR2TMB
- (near D12) CAN CONVERTER SUR2GCB
- RS-485  STEND
- Labels drawn without touching a wire or pin: SYS_RESETn

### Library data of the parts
D10 D12 = TCAN1051VDQ1: CAN Transceiver 8-SOIC 5V; ValueManufacturer: Texas Instruments; PowerVoltage: 4.5V~5.5V; ValueDescription: TCAN1051VDQ1  CAN приемопередатчик 4.5V~5.5V  8-SOIC (3.90mm)
D11 = SN65HVD3086EDG: RS422 RS485 FULL Transceiver 8-SOIC 5V; ValueManufacturer: Texas Instruments; PowerVoltage: 4.5V~5.5V; ValueDescription: SN65HVD3086EDG  FULL RS485/RS422 приемопередатчик 4.5V~5.5V  10-SOP (3.00mm)
R65 = R-0402-1%: SMD 0402 0.1Вт ±1% 50В; ValueManufacturer: Panasonic; ValueManufacturerPartNumber: ERJ-2RK; PowerVoltage: 0.1Вт 50В; ValueDescription: 0402 (1005)  0.1Вт 50В  33Ом ±1%; ValueType: Chip Resistor
R66 R68 R69 = R-0603-5%: SMD 0603 0.1Вт ±5% 75В; ValueManufacturer: Panasonic; ValueManufacturerPartNumber: ERJ-3GE; PowerVoltage: 0.1Вт 75В; ValueDescription: 0603 (1608)  0.1Вт 75В  4.7кОм ±5%; ValueType: Chip Resistor
R67 R70 = R-0603-5%: SMD 0603 0.1Вт ±5% 75В; ValueManufacturer: Panasonic; ValueManufacturerPartNumber: ERJ-3GE; PowerVoltage: 0.1Вт 75В; ValueDescription: 0603 (1608)  0.1Вт 75В  51кОм ±5%; ValueType: Chip Resistor
X17 = DF17(4.0)-40DP-0.5V(57): CONN HEADER 40POS .5MM SMD W/FIT; ValueManufacturer: Hirose Electric Co Ltd; PowerVoltage: 50V; TechSpec: Шаг 0.5; ValueDescription: DF17(4.0)-40DP-0.5V(57) Двухрядная вилка Hirose Electric Co Ltd  15.2x4.7mm  Шаг 0.5; ValueType: Connector
X18 = DF17(4.0)-80DP-0.5V(57): CONN HEADER 80POS .5MM SMD W/FIT; ValueManufacturer: Hirose Electric Co Ltd; PowerVoltage: 50V; TechSpec: Шаг 0.5; ValueDescription: DF17(4.0)-80DP-0.5V(57) Двухрядная вилка Hirose Electric Co Ltd  25.2x4.7mm  Шаг 0.5; ValueType: Connector

## Sheet SUR2MCB_P3_POWERETHERNNET.SchDoc
size 420 x 297 mm; Scale: 1:1; Разраб.: Иванов; Обозначение документа: АБВГ.123456.001 Э3; Пров.: Петров; Утв.: Сидоров; Наименование организации: ОАО "Концерн "МПО-Гидроприбор"; Перв. применение: АБВГ.123456.000; Наименование изделия 1: Плата; Наименование изделия 2: Схема электрическая; Наименование изделия 3: принципиальная; Нач. отд.: Нач. отд.; Фамилия нач. отд.: Сидоров
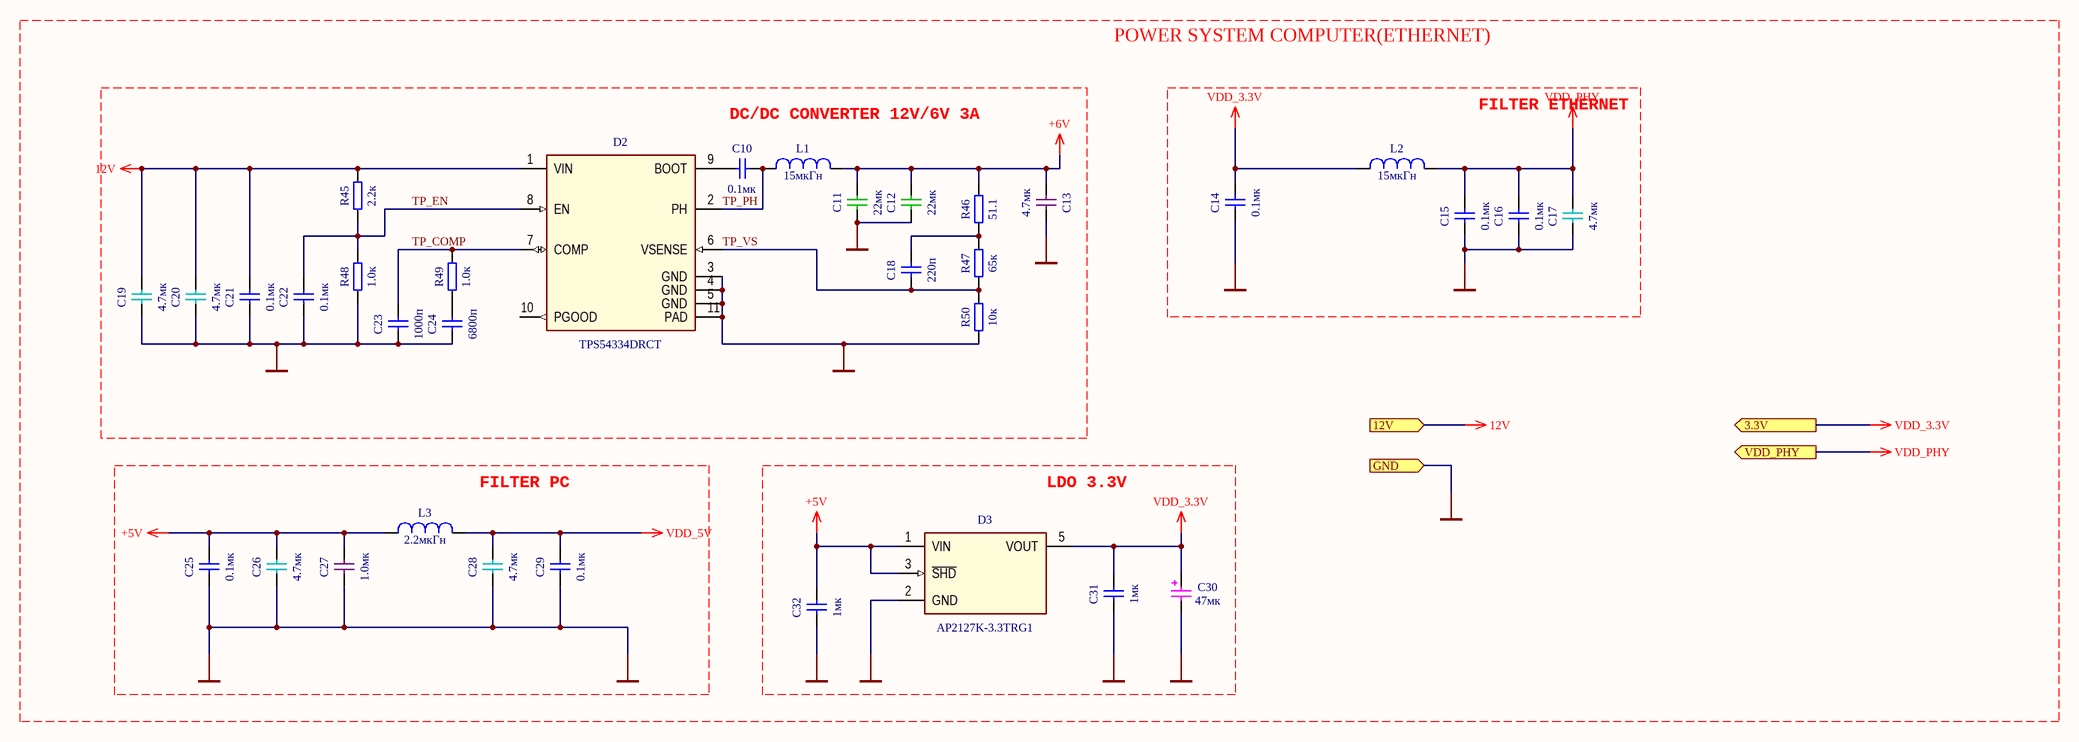
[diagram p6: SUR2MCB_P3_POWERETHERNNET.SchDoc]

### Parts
C10  value 0.1мк  [C0603]
C11  value 22мк  [C1210]
C12  value 22мк  [C1210]
C13  value 4.7мк  [C0805]
C14  value 0.1мк  [C0603]
C15  value 0.1мк  [C0603]
C16  value 0.1мк  [C0603]
C17  value 4.7мк  [C1206]
C18  value 220п  [C0603]
C19  value 4.7мк  [C1206]
C20  value 4.7мк  [C1206]
C21  value 0.1мк  [C0603]
C22  value 0.1мк  [C0603]
C23  value 1000п  [C0603]
C24  value 6800п  [C0603]
C25  value 0.1мк  [C0603]
C26  value 4.7мк  [C1206]
C27  value 1.0мк  [C0805]
C28  value 4.7мк  [C1206]
C29  value 0.1мк  [C0603]
C30  value 47мк  [CAP_ELEC_SIZE_G]
C31  value 1мк  [C0603]
C32  value 1мк  [C0603]
D2  value TPS54334DRCT  [SON-10-3X3-0.5-T-SPECIAL]
D3  value AP2127K-3.3TRG1  [TSOT23-5-1.4X3-0.95]
L1  value 15мкГн  [L-ASPI-0630LR]
L2  value 15мкГн  [L-ASPI-0630LR]
L3  value 2.2мкГн  [L1008]
R45  value 2.2к  [R0603]
R46  value 51.1  [R0603]
R47  value 65к  [R0603]
R48  value 1.0к  [R0603]
R49  value 1.0к  [R0603]
R50  value 10к  [R0603]

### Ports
3.3V (out), 12V (in), GND (in), VDD_PHY (out)

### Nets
12V: C19.2 C20.2 C21.2 D2.1(VIN) R45.1 ; port 12V  [project net +12V]
+5V: C25.2 C26.2 C27.2 C32.2 D3.1(VIN) D3.3(~{SHD}) L3.1
+6V: C11.2 C12.2 C13.1 L1.2 R46.1
GND: C11.1 C12.1 C13.2 C14.1 C15.1 C16.1 C17.1 C19.1 C20.1 C21.1 C22.1 C23.1 C24.1 C25.1 C26.1 C27.1 C28.1 C29.1 C30.1 C31.1 C32.1 D2.3(GND) D2.4(GND) D2.5(GND) D2.11(PAD) D3.2(GND) R48.2 R50.2 ; port GND  [project net О1]
VDD_3.3V: C14.2 C30.2 C31.2 D3.5(VOUT) L2.1 ; port 3.3V
VDD_5V: C28.2 C29.2 L3.2
VDD_PHY: C15.2 C16.2 C17.2 L2.2 ; port VDD_PHY
TP_COMP: C23.2 D2.7(COMP) R49.1
TP_EN: C22.2 D2.8(EN) R45.2 R48.1
TP_PH: C10.2 D2.2(PH) L1.1
TP_VS: C18.1 D2.6(VSENSE) R47.2 R50.1
NetC10_1: C10.1 D2.9(BOOT)
NetC18_2: C18.2 R46.2 R47.1
NetC24_2: C24.2 R49.2

Not connected (* = marked no-connect by the designer): D2 10(PGOOD)

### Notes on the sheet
- POWER SYSTEM COMPUTER(ETHERNET)
- FILTER ETHERNET
- DC/DC CONVERTER 12V/6V 3A
- (near L3) FILTER PC
- LDO 3.3V

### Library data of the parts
C10 C14-C16 C21 C22 C25 C29 = C-0603: as C9 on sheet SUR2MCB_P2_CONVETHERNET
C11 C12 = C-1210: SMD X7R 1210 250В ±10%; ValueManufacturer: Murata Electronics; ValueManufacturerPartNumber: GCJ32DR72E; ValueDescription: X7R 1210 (3225)  250В  22мкФ ±10%; ValueType: Ceramic Capacitor
C13 = C-0805: SMD X7R 0805 50В ±10%; ValueManufacturer: Murata Electronics; ValueManufacturerPartNumber: GCM21BR71H; ValueDescription: X7R 0805 (2012)  50В  4.7мкФ ±10%; ValueType: Ceramic Capacitor
C17 C19 C20 C26 C28 = C-1206: SMD X7R 1206 100В ±10%; ValueManufacturer: Murata Electronics; ValueManufacturerPartNumber: GCM319R72A; ValueDescription: X7R 1206 (3216)  100В  4.7мкФ ±10%; ValueType: Ceramic Capacitor
C18 = C-0603: SMD X7R 0603 25В ±10%; ValueManufacturer: Murata Electronics; ValueManufacturerPartNumber: GCM188R71H; ValueDescription: X7R 0603 (1608)  25В  220пФ ±10%; ValueType: Ceramic Capacitor
C23 = C-0603: SMD X7R 0603 25В ±10%; ValueManufacturer: Murata Electronics; ValueManufacturerPartNumber: GCM188R71H; ValueDescription: X7R 0603 (1608)  25В  1000пФ ±10%; ValueType: Ceramic Capacitor
C24 = C-0603: SMD X7R 0603 25В ±10%; ValueManufacturer: Murata Electronics; ValueManufacturerPartNumber: GCM188R71H; ValueDescription: X7R 0603 (1608)  25В  6800пФ ±10%; ValueType: Ceramic Capacitor
C27 = C-0805: SMD X7R 0805 50В ±10%; ValueManufacturer: Murata Electronics; ValueManufacturerPartNumber: GCM21BR71H; ValueDescription: X7R 0805 (2012)  50В  1.0мкФ ±10%; ValueType: Ceramic Capacitor
C30 = C-EL-SMD-D10: SMD CAP ALUM 47UF 20% 50V 10.30x10.30mm; ValueManufacturer: Panasonic Electronic; ValueManufacturerPartNumber: EEE-FC1H470P; PowerVoltage: 50B; ValueDescription: EEE-FC1H470P  50B  47мкФ ±20%  10.30x10.30mm; ValueType: Electrolytic Capacitor
C31 C32 = C-0603: as C6 on sheet SUR2MCB_P2_CONVETHERNET
D2 = TPS54334DRCT: Step Down 4.2V~28V Input voltage 3A 570kHz; ValueManufacturer: Texas Instruments; PowerVoltage: 4.2V~28V 3A; ValueDescription: TPS54334DRCT  Преобразователь напряжения 4.2V~28V 3A  10-VSON EP (3x3mm); ValueType: Power Management
D3 = AP2127K-3.3TRG1: LDO 3.3V 300mA VINmax=6V SOT-23-5 SOT-753; ValueManufacturer: Diodes Incorporated; ValueDescription: AP2127K-3.3TRG1 Линейный преобразователь 3.3V 300mA  SOT-23-5 (SOT-753)  VINmax=6V; ValueType: Power Management
L1 L2 = L-ASPI-0630LR-150M: FIXED IND 15UH 3A 120 MOHM; ValueManufacturer: Abracon LLC; Tolerance: ±20%; ValueDescription: ASPI-0630LR-150M Индуктивность 15мкГн  7.20x6.65mm  3A  ±20%; ValueType: Inductor
L3 = L-CIG22B2R2MNE: FIXED IND 2.2UH 1.1A 183 MOHM; ValueManufacturer: Samsung Electro-Mechanics; Tolerance: ±20%; ValueDescription: CIG22B2R2MNE Индуктивность 2.2мкГн  1008 (2520)  1.1A  ±20%; ValueType: Inductor
R45 = R-0603-5%: SMD 0603 0.1Вт ±5% 75В; ValueManufacturer: Panasonic; ValueManufacturerPartNumber: ERJ-3GE; PowerVoltage: 0.1Вт 75В; ValueDescription: 0603 (1608)  0.1Вт 75В  2.2кОм ±5%; ValueType: Chip Resistor
R46 = R-0603-5%: SMD 0603 0.1Вт ±5% 75В; ValueManufacturer: Panasonic; ValueManufacturerPartNumber: ERJ-3GE; PowerVoltage: 0.1Вт 75В; ValueDescription: 0603 (1608)  0.1Вт 75В  51.1Ом ±5%; ValueType: Chip Resistor
R47 = R-0603-5%: SMD 0603 0.1Вт ±5% 75В; ValueManufacturer: Panasonic; ValueManufacturerPartNumber: ERJ-3GE; PowerVoltage: 0.1Вт 75В; ValueDescription: 0603 (1608)  0.1Вт 75В  65кОм ±5%; ValueType: Chip Resistor
R48 R49 = R-0603-5%: SMD 0603 0.1Вт ±5% 75В; ValueManufacturer: Panasonic; ValueManufacturerPartNumber: ERJ-3GE; PowerVoltage: 0.1Вт 75В; ValueDescription: 0603 (1608)  0.1Вт 75В  1.0кОм ±5%; ValueType: Chip Resistor
R50 = R-0603-5%: SMD 0603 0.1Вт ±5% 75В; ValueManufacturer: Panasonic; ValueManufacturerPartNumber: ERJ-3GE; PowerVoltage: 0.1Вт 75В; ValueDescription: 0603 (1608)  0.1Вт 75В  10кОм ±5%; ValueType: Chip Resistor

## Sheet SUR2MCB_P4_CONVERTINTERFACES.SchDoc
size 420 x 297 mm; Scale: 1:1; Обозначение документа: АБВГ.123456.001 Э3
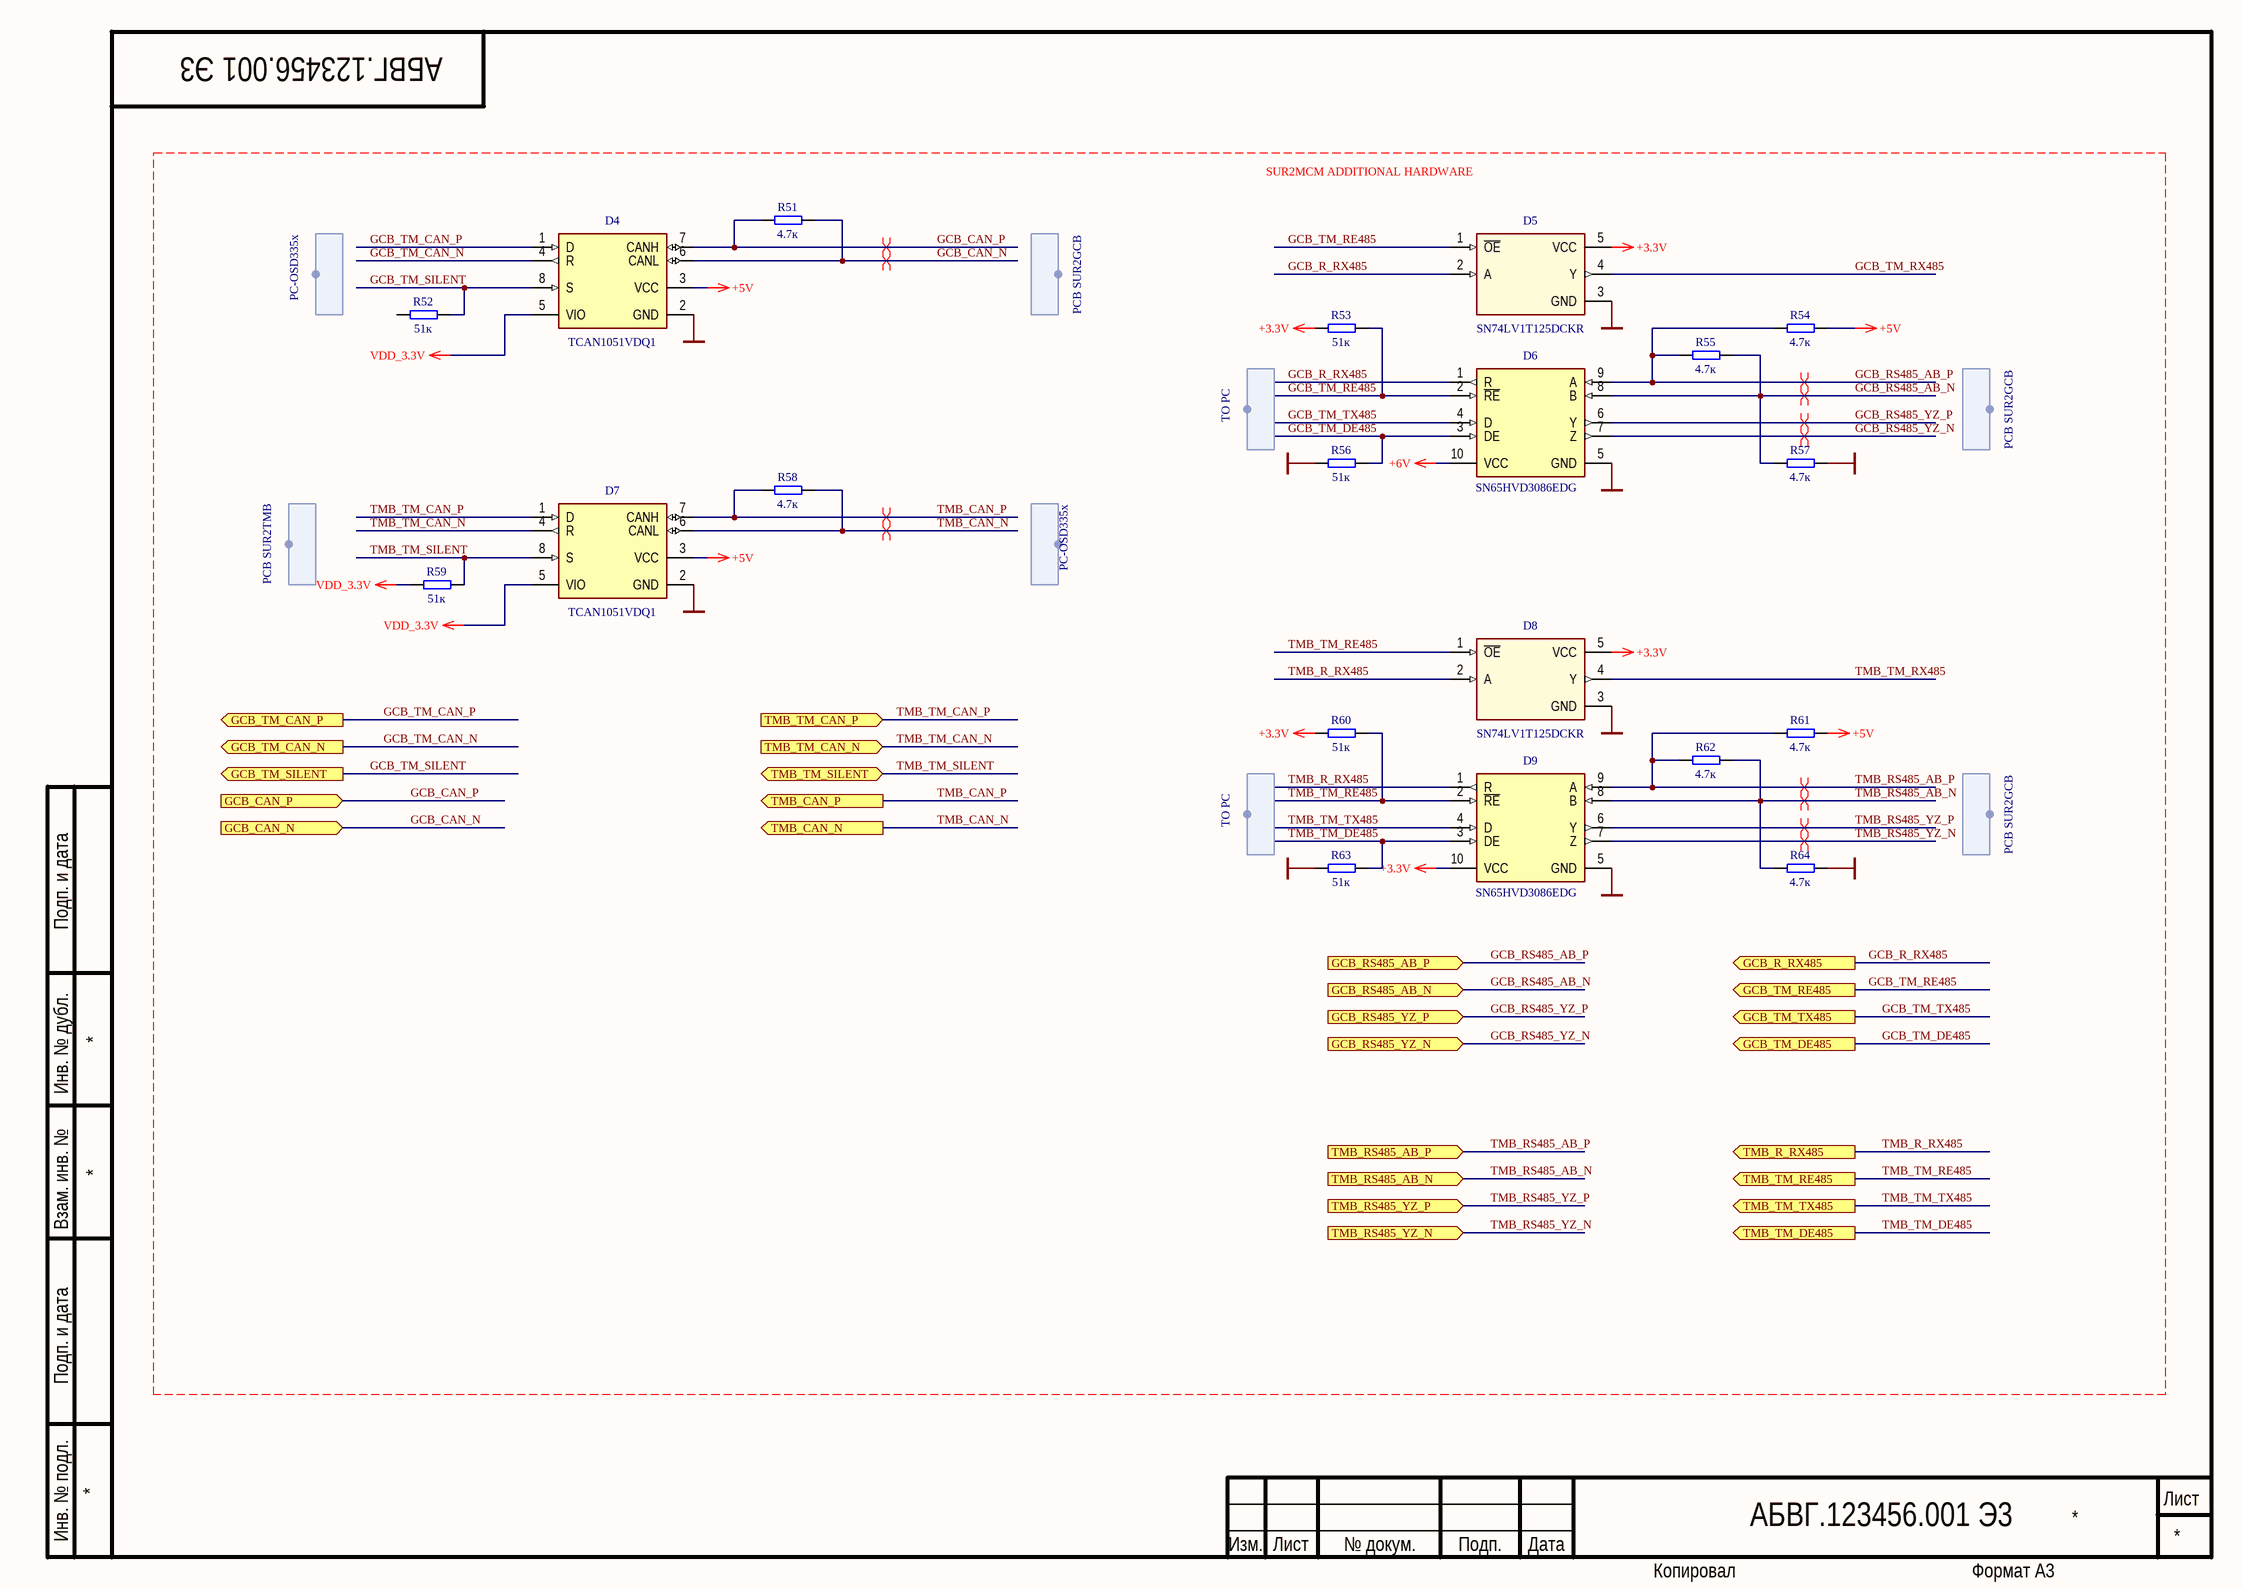
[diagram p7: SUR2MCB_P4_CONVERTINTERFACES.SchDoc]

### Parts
D4  value TCAN1051VDQ1  [SOP-8-3.9X5-1.27]
D5  value SN74LV1T125DCKR  [SOT353-5-1.25X2.1-0.65]
D6  value SN65HVD3086EDG  [MSOP-10-3X3-0.5]
D7  value TCAN1051VDQ1  [SOP-8-3.9X5-1.27]
D8  value SN74LV1T125DCKR  [SOT353-5-1.25X2.1-0.65]
D9  value SN65HVD3086EDG  [MSOP-10-3X3-0.5]
R51  value 4.7к  [R0603]
R52  value 51к  [R0603]
R53  value 51к  [R0603]
R54  value 4.7к  [R0603]
R55  value 4.7к  [R0603]
R56  value 51к  [R0603]
R57  value 4.7к  [R0603]
R58  value 4.7к  [R0603]
R59  value 51к  [R0603]
R60  value 51к  [R0603]
R61  value 4.7к  [R0603]
R62  value 4.7к  [R0603]
R63  value 51к  [R0603]
R64  value 4.7к  [R0603]

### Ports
GCB_CAN_N (in), GCB_CAN_P (in), GCB_R_RX485 (out), GCB_RS485_AB_N (in), GCB_RS485_AB_P (in), GCB_RS485_YZ_N (in), GCB_RS485_YZ_P (in), GCB_TM_CAN_N (out), GCB_TM_CAN_P (out), GCB_TM_DE485 (out), GCB_TM_RE485 (out), GCB_TM_SILENT (out), GCB_TM_TX485 (out), TMB_CAN_N (out), TMB_CAN_P (out), TMB_R_RX485 (out), TMB_RS485_AB_N (in), TMB_RS485_AB_P (in), TMB_RS485_YZ_N (in), TMB_RS485_YZ_P (in), TMB_TM_CAN_N (in), TMB_TM_CAN_P (in), TMB_TM_DE485 (out), TMB_TM_RE485 (out), TMB_TM_SILENT (bidir), TMB_TM_TX485 (out)

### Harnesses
PC-OSD335x: 
PCB SUR2GCB: 
PCB SUR2TMB: 
TO PC: 

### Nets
+3.3V: D5.5(VCC) D8.5(VCC) D9.10(VCC) R53.2 R60.2
+5V: D4.3(VCC) D7.3(VCC) R54.1 R61.1
+6V: D6.10(VCC)
GND: D4.2(GND) D5.3(GND) D6.5(GND) D7.2(GND) D8.3(GND) D9.5(GND) R56.2 R57.1 R63.2 R64.1  [project net О1]
VDD_3.3V: D4.5(VIO) D7.5(VIO) R59.2
GCB_CAN_N: D4.6(CANL) R51.1 ; port GCB_CAN_N
GCB_CAN_P: D4.7(CANH) R51.2 ; port GCB_CAN_P
GCB_R_RX485: D5.2(A) D6.1(R) ; port GCB_R_RX485
GCB_RS485_AB_N: D6.8(B) R55.1 R57.2 ; port GCB_RS485_AB_N
GCB_RS485_AB_P: D6.9(A) R54.2 R55.2 ; port GCB_RS485_AB_P
GCB_RS485_YZ_N: D6.7(Z) ; port GCB_RS485_YZ_N
GCB_RS485_YZ_P: D6.6(Y) ; port GCB_RS485_YZ_P
GCB_TM_CAN_N: D4.4(R) ; port GCB_TM_CAN_N
GCB_TM_CAN_P: D4.1(D) ; port GCB_TM_CAN_P
GCB_TM_DE485: D6.3(DE) R56.1 ; port GCB_TM_DE485
GCB_TM_RE485: D5.1(~{OE}) D6.2(~{RE}) R53.1 ; port GCB_TM_RE485
GCB_TM_RX485: D5.4(Y)
GCB_TM_SILENT: D4.8(S) R52.1 ; port GCB_TM_SILENT
GCB_TM_TX485: D6.4(D) ; port GCB_TM_TX485
TMB_CAN_N: D7.6(CANL) R58.1 ; port TMB_CAN_N
TMB_CAN_P: D7.7(CANH) R58.2 ; port TMB_CAN_P
TMB_R_RX485: D8.2(A) D9.1(R) ; port TMB_R_RX485
TMB_RS485_AB_N: D9.8(B) R62.1 R64.2 ; port TMB_RS485_AB_N
TMB_RS485_AB_P: D9.9(A) R61.2 R62.2 ; port TMB_RS485_AB_P
TMB_RS485_YZ_N: D9.7(Z) ; port TMB_RS485_YZ_N
TMB_RS485_YZ_P: D9.6(Y) ; port TMB_RS485_YZ_P
TMB_TM_CAN_N: D7.4(R) ; port TMB_TM_CAN_N  [project net TEST_CAN_N]
TMB_TM_CAN_P: D7.1(D) ; port TMB_TM_CAN_P  [project net TEST_CAN_P]
TMB_TM_DE485: D9.3(DE) R63.1 ; port TMB_TM_DE485
TMB_TM_RE485: D8.1(~{OE}) D9.2(~{RE}) R60.1 ; port TMB_TM_RE485
TMB_TM_RX485: D8.4(Y)
TMB_TM_SILENT: D7.8(S) R59.1 ; port TMB_TM_SILENT
TMB_TM_TX485: D9.4(D) ; port TMB_TM_TX485

Not connected (* = marked no-connect by the designer): R52 2

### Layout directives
differential pair: GCB_CAN_N, GCB_CAN_P, GCB_RS485_AB_N, GCB_RS485_AB_P, GCB_RS485_YZ_N, GCB_RS485_YZ_P, TMB_CAN_N, TMB_CAN_P, TMB_RS485_AB_N, TMB_RS485_AB_P, TMB_RS485_YZ_N, TMB_RS485_YZ_P

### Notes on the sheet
- SUR2MCM ADDITIONAL HARDWARE

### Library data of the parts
D4 D7 = TCAN1051VDQ1: as D10 on sheet SUR2MCB_P5_PC
D5 D8 = SN74LV1T125DCKR: BUFFER GATE SHIFT LEVEL CMOS SC70-5; ValueManufacturer: Texas Instruments; PowerVoltage: 1.6V~5.5V; TechSpec: 50MHz; ValueDescription: SN74LV1T125DCKR Преобраз. логич. уровня 1.6V~5.5V  SC-70-5  50MHz
D6 D9 = SN65HVD3086EDG: as D11 on sheet SUR2MCB_P5_PC
R51 R54 R55 R57 R58 R61 R62 R64 = R-0603-5%: as R66 on sheet SUR2MCB_P5_PC
R52 R53 R56 R59 R60 R63 = R-0603-5%: as R67 on sheet SUR2MCB_P5_PC

## Sheet Struct_E1.SchDoc
size 420 x 297 mm; Scale: 1:1; Разраб.: Иванов; Обозначение документа: АБВГ.123456.001 Э3; Пров.: Петров; Утв.: Сидоров; Наименование организации: ОАО "Концерн "МПО-Гидроприбор"; Перв. применение: АБВГ.123456.000; Наименование изделия 1: Плата; Наименование изделия 2: Схема электрическая; Наименование изделия 3: принципиальная; Нач. отд.: Нач. отд.; Фамилия нач. отд.: Сидоров
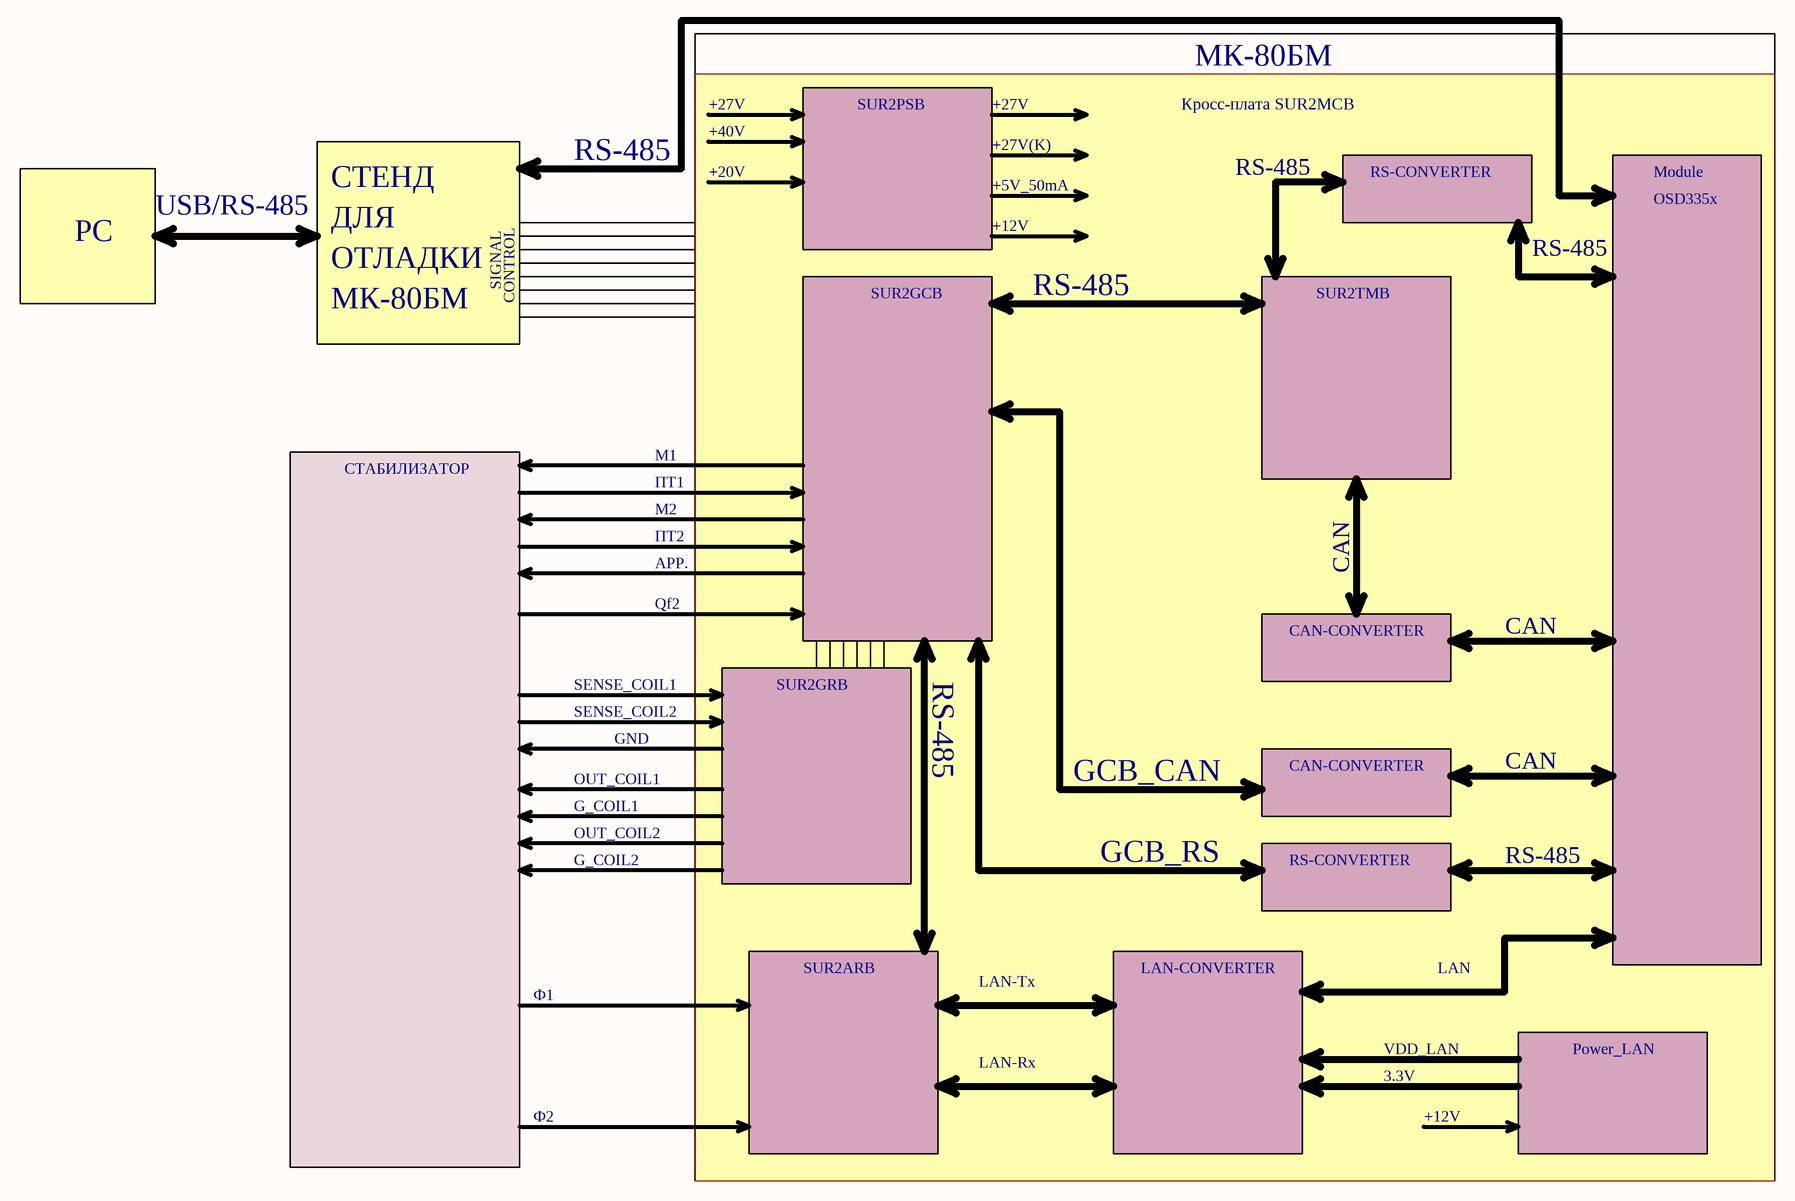
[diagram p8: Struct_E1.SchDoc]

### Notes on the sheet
- +27V
- SUR2PSB
- Кросс-плата SUR2MCB
- МК-80БМ
- СТЕНД
- RS-485
- +40V
- +20V
- +27V(K)
- +5V_50mA
- RS-CONVERTER
- Module
- PC
- USB/RS-485
- ДЛЯ
- +12V
- OSD335x
- ОТЛАДКИ
- SIGNAL
- CONTROL
- SUR2GCB
- SUR2TMB
- M1
- СТАБИЛИЗАТОР
- M2
- ПТ1
- ПТ2
- АРР.
- CAN
- Qf2
- CAN-CONVERTER
- SENSE_COIL1
- SENSE_COIL2
- SUR2GRB
- OUT_COIL1
- GND
- GCB_CAN
- OUT_COIL2
- G_COIL1
- G_COIL2
- GCB_RS
- Ф1
- SUR2ARB
- LAN-Tx
- LAN-CONVERTER
- LAN
- LAN-Rx
- VDD_LAN
- Power_LAN
- Ф2
- 3.3V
